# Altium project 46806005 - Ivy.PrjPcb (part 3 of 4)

## Sheet 620_Ethernet2.SchDoc: Ivy - Verdin Industrial Board Rev 1.1
size Letter; Organization: Toradex Solutions Inc.; Address1: 6415 Northwest Drive; Address2: Mississauga, ON, L4V 1X1; Address3: Canada
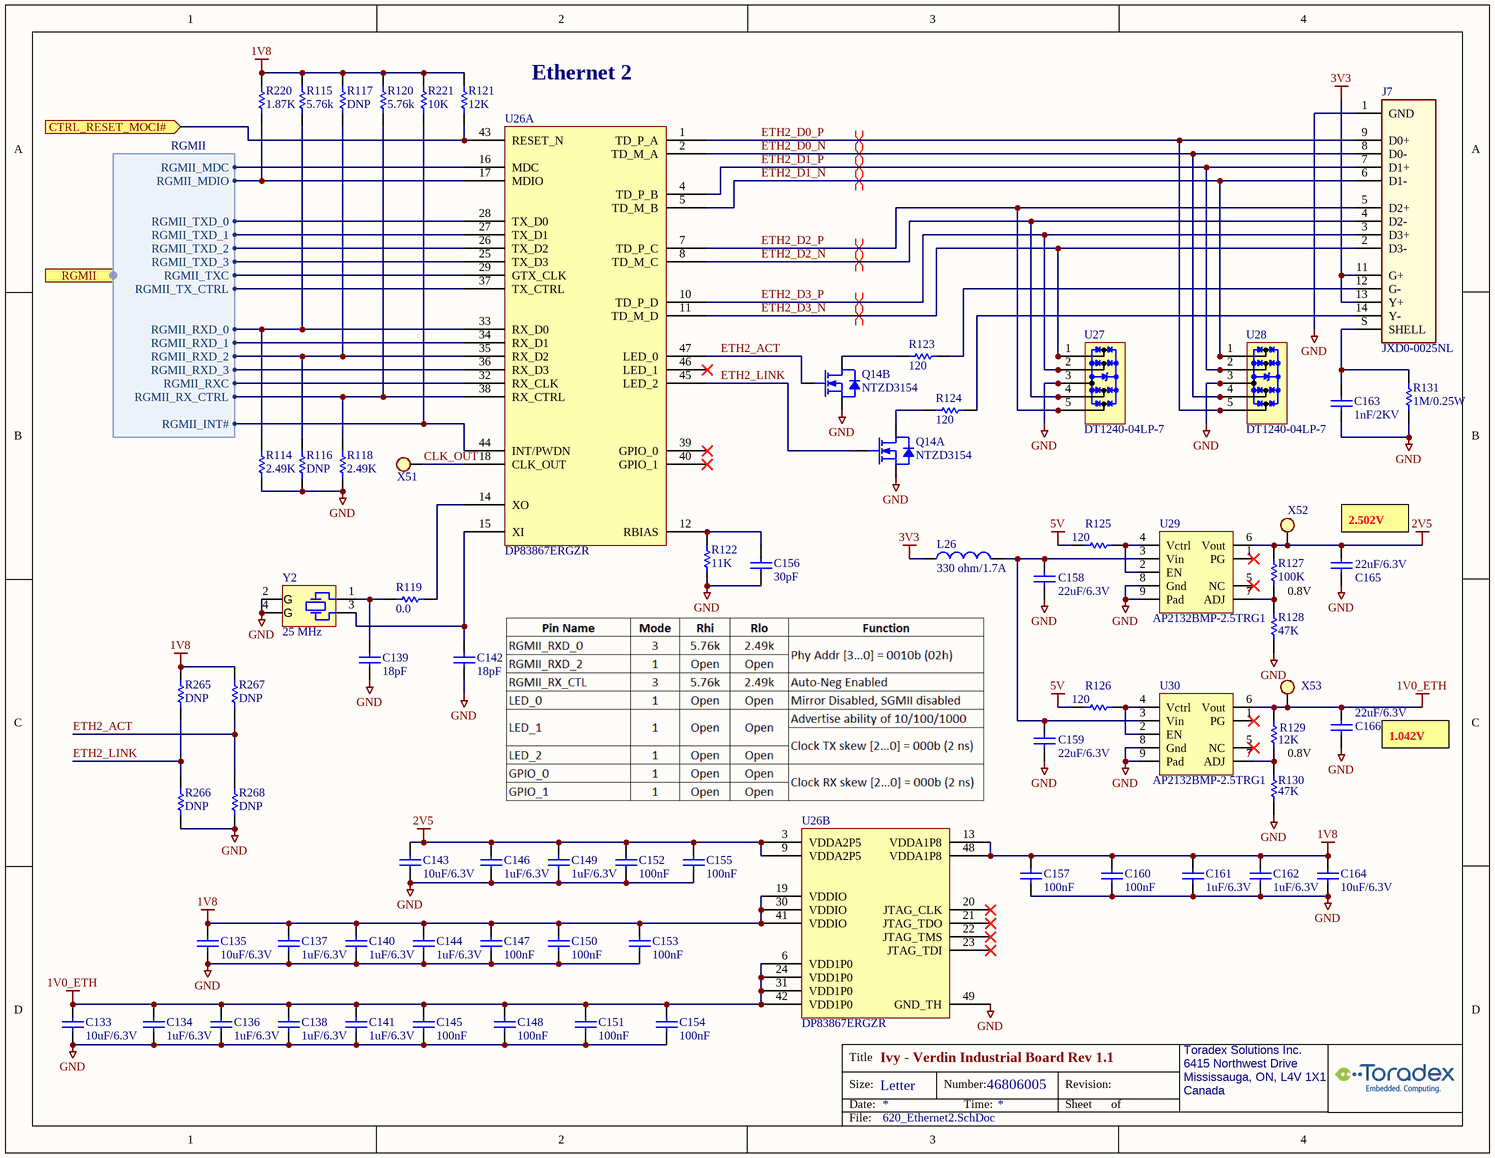
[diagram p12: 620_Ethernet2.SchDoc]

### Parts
C133  value 10uF/6.3V  [C0402_CAPC1005L]  (hidden comment: 1646-Cap-0402-10uF/6.3V)
C134  value 1uF/6.3V  [C0402_CAPC1005L]  (hidden comment: 1006-Cap-0402-1uF/6V3)
C135  value 10uF/6.3V  [C0402_CAPC1005L]  (hidden comment: 1646-Cap-0402-10uF/6.3V)
C136  value 1uF/6.3V  [C0402_CAPC1005L]  (hidden comment: 1006-Cap-0402-1uF/6V3)
C137  value 1uF/6.3V  [C0402_CAPC1005L]  (hidden comment: 1006-Cap-0402-1uF/6V3)
C138  value 1uF/6.3V  [C0402_CAPC1005L]  (hidden comment: 1006-Cap-0402-1uF/6V3)
C139  value 18pF  [C0402_CAPC1005L]  (hidden comment: 0321-Cap-0402-18pF/50V)
C140  value 1uF/6.3V  [C0402_CAPC1005L]  (hidden comment: 1006-Cap-0402-1uF/6V3)
C141  value 1uF/6.3V  [C0402_CAPC1005L]  (hidden comment: 1006-Cap-0402-1uF/6V3)
C142  value 18pF  [C0402_CAPC1005L]  (hidden comment: 0321-Cap-0402-18pF/50V)
C143  value 10uF/6.3V  [C0402_CAPC1005L]  (hidden comment: 1646-Cap-0402-10uF/6.3V)
C144  value 1uF/6.3V  [C0402_CAPC1005L]  (hidden comment: 1006-Cap-0402-1uF/6V3)
C145  100nF  [C0402_CAPC1005L]
C146  value 1uF/6.3V  [C0402_CAPC1005L]  (hidden comment: 1006-Cap-0402-1uF/6V3)
C147  100nF  [C0402_CAPC1005L]
C148  100nF  [C0402_CAPC1005L]
C149  value 1uF/6.3V  [C0402_CAPC1005L]  (hidden comment: 1006-Cap-0402-1uF/6V3)
C150  100nF  [C0402_CAPC1005L]
C151  100nF  [C0402_CAPC1005L]
C152  100nF  [C0402_CAPC1005L]
C153  100nF  [C0402_CAPC1005L]
C154  100nF  [C0402_CAPC1005L]
C155  100nF  [C0402_CAPC1005L]
C156  value 30pF  [C/0603]  (hidden comment: 0958-Cap-0603-30pF/50V)
C157  100nF  [C0402_CAPC1005L]
C158  22uF/6.3V  [C0402_CAPC1005L]
C159  22uF/6.3V  [C0402_CAPC1005L]
C160  100nF  [C0402_CAPC1005L]
C161  value 1uF/6.3V  [C0402_CAPC1005L]  (hidden comment: 1006-Cap-0402-1uF/6V3)
C162  value 1uF/6.3V  [C0402_CAPC1005L]  (hidden comment: 1006-Cap-0402-1uF/6V3)
C163  value 1nF/2KV  [C/1206]  (hidden comment: 0567-Cap-1206-1nF/2KV)
C164  value 10uF/6.3V  [C0402_CAPC1005L]  (hidden comment: 1646-Cap-0402-10uF/6.3V)
C165  22uF/6.3V  [C0402_CAPC1005L]
C166  22uF/6.3V  [C0402_CAPC1005L]
J7  JXD0-0025NL  [PULSE_JXD0-0025NL]
L26  value 330 ohm/1.7A  [INDC1608x095]  (hidden comment: 0405-Fer-0603-330ohm/1.7A)
Q14  NTZD3154  [SOT563]  (parts A,B of 2)
R114  value 2.49K  [R0402_RESC1005L]  (hidden comment: 2313-Res-0402-2.49K)
R115  value 5.76k  [R0402_RESC1005L]  (hidden comment: 2077-Res-0402-5.76K)
R116  value DNP  [R0402_RESC1005L]  (hidden comment: 0000-Res-0402-DNP)
R117  value DNP  [R0402_RESC1005L]  (hidden comment: 0000-Res-0402-DNP)
R118  value 2.49K  [R0402_RESC1005L]  (hidden comment: 2313-Res-0402-2.49K)
R119  value 0.0  [R/0603]  (hidden comment: 0195-Res-0603-0.0ohm)
R120  value 5.76k  [R0402_RESC1005L]  (hidden comment: 2077-Res-0402-5.76K)
R121  value 12K  [R0402_RESC1005L]  (hidden comment: 1537-Res-0402-12K)
R122  value 11K  [R0402_RESC1005L]  (hidden comment: 2527-Res-0402-11K)
R123  value 120  [R0402_RESC1005L]  (hidden comment: 1552-Res-0402-120)
R124  value 120  [R0402_RESC1005L]  (hidden comment: 1552-Res-0402-120)
R125  value 120  [R0402_RESC1005L]  (hidden comment: 1552-Res-0402-120)
R126  value 120  [R0402_RESC1005L]  (hidden comment: 1552-Res-0402-120)
R127  value 100K  [R0402_RESC1005L]  (hidden comment: 1977-Res-0402-100K)
R128  value 47K  [R/0603]  (hidden comment: 0042-Res-0603-47K)
R129  value 12K  [R0402_RESC1005L]  (hidden comment: 1537-Res-0402-12K)
R130  value 47K  [R/0603]  (hidden comment: 0042-Res-0603-47K)
R131  value 1M/0.25W  [R/1206]  (hidden comment: 1860-Res-1206-1M-5%-0.25W)
R220  value 1.87K  [R0402_RESC1005L]  (hidden comment: 1536-Res-0402-1.87K)
R221  value 10K  [R0402_RESC1005L]  (hidden comment: 1572-Res-0402-10K)
R265  value DNP  [R0402_RESC1005L]  (hidden comment: 0000-Res-0402-DNP)
R266  value DNP  [R0402_RESC1005L]  (hidden comment: 0000-Res-0402-DNP)
R267  value DNP  [R0402_RESC1005L]  (hidden comment: 0000-Res-0402-DNP)
R268  value DNP  [R0402_RESC1005L]  (hidden comment: 0000-Res-0402-DNP)
U26  DP83867ERGZR  [RGZ0048B]  (parts A,B of 2)
U27  DT1240-04LP-7  [10-UFDFN]
U28  DT1240-04LP-7  [10-UFDFN]
U29  AP2132BMP-2.5TRG1  [SOP-9 TP_ALT]
U30  AP2132BMP-2.5TRG1  [SOP-9 TP_ALT]
X51  000-TestPoint2  [TestPoint_3]  (value not drawn)
X52  000-TestPoint2  [TestPoint_3]  (value not drawn)
X53  000-TestPoint2  [TestPoint_3]  (value not drawn)
Y2  value 25 MHz  [XTAL_CX3225]  (hidden comment: 0987-Xtal 25MHz 3.2x2.5mm)

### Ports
CTRL_RESET_MOCI# (in), RGMII (harness RGMII)

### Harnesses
RGMII: RGMII_TXD_0, RGMII_TXD_1, RGMII_TXD_2, RGMII_TXD_3, RGMII_TXC, RGMII_TX_CTRL, RGMII_RXD_0, RGMII_RXD_1, RGMII_RXD_2, RGMII_RXD_3, RGMII_RXC, RGMII_RX_CTRL, RGMII_MDIO, RGMII_MDC, RGMII_INT#

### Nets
1V0_ETH: C133.2 C134.2 C136.2 C138.2 C141.2 C145.2 C148.2 C151.2 C154.2 C166.2 R129.2 U26.6(VDD1P0) U26.24(VDD1P0) U26.31(VDD1P0) U26.42(VDD1P0) U30.6(Vout) X53.1
1V8: C135.2 C137.2 C140.2 C144.2 C147.2 C150.2 C153.2 C157.2 C160.2 C161.2 C162.2 C164.2 R115.2 R117.1 R120.2 R121.2 R220.2 R221.2 R265.1 R267.1 U26.13(VDDA1P8) U26.19(VDDIO) U26.30(VDDIO) U26.41(VDDIO) U26.48(VDDA1P8)
2V5: C143.2 C146.2 C149.2 C152.2 C155.2 C165.2 R127.2 U26.3(VDDA2P5) U26.9(VDDA2P5) U29.6(Vout) X52.1
3V3: J7.11(G+) J7.13(Y+) L26.1
5V: R125.2 R126.2
GND: C133.1 C134.1 C135.1 C136.1 C137.1 C138.1 C139.1 C140.1 C141.1 C142.1 C143.1 C144.1 C145.1 C146.1 C147.1 C148.1 C149.1 C150.1 C151.1 C152.1 C153.1 C154.1 C155.1 C156.1 C157.1 C158.1 C159.1 C160.1 C161.1 C162.1 C163.1 C164.1 C165.1 C166.1 J7.1(GND) Q14.1(S) Q14.4(S) R114.1 R116.1 R118.1 R122.2 R128.2 R130.2 R131.2 R266.2 R268.2 U26.49(GND_TH) U27.3(GND) U27.8(GND) U28.3(GND) U28.8(GND) U29.8(Gnd) U29.9(Pad) U30.8(Gnd) U30.9(Pad) Y2.2(GND) Y2.4(GND)
CLK_OUT: U26.18(CLK_OUT) X51.1
CTRL_RESET_MOCI#: R121.1 U26.43(RESET_N) ; port CTRL_RESET_MOCI#
ETH2_ACT: Q14.5(G) R267.2 R268.1 U26.47(LED_0)
ETH2_D0_N: J7.8(D0-) U26.2(TD_M_A) U28.4(IO3) U28.7(NC)
ETH2_D0_P: J7.9(D0+) U26.1(TD_P_A) U28.5(IO4) U28.6(NC)
ETH2_D1_N: J7.6(D1-) U26.5(TD_M_B) U28.1(IO1) U28.10(NC)
ETH2_D1_P: J7.7(D1+) U26.4(TD_P_B) U28.2(IO2) U28.9(NC)
ETH2_D2_N: J7.4(D2-) U26.8(TD_M_C) U27.4(IO3) U27.7(NC)
ETH2_D2_P: J7.5(D2+) U26.7(TD_P_C) U27.5(IO4) U27.6(NC)
ETH2_D3_N: J7.2(D3-) U26.11(TD_M_D) U27.1(IO1) U27.10(NC)
ETH2_D3_P: J7.3(D3+) U26.10(TD_P_D) U27.2(IO2) U27.9(NC)
ETH2_LINK: Q14.2(G) R265.2 R266.1 U26.45(LED_2)
NetC139_2: C139.2 R119.2 Y2.1
NetC142_2: C142.2 U26.15(XI) Y2.3
NetC156_2: C156.2 R122.1 U26.12(RBIAS)
NetC158_2: C158.2 C159.2 L26.2 U29.3(Vin) U30.3(Vin)
NetC163_2: C163.2 J7.S(SHELL) R131.1
NetJ7_12: J7.12(G-) R123.2
NetJ7_14: J7.14(Y-) R124.2
NetM1_189: R221.1 U26.44(INT/PWDN) ; port RGMII.RGMII_INT#
NetM1_191: R220.1 U26.17(MDIO) ; port RGMII.RGMII_MDIO
NetM1_193: U26.16(MDC) ; port RGMII.RGMII_MDC
NetM1_197: U26.32(RX_CLK) ; port RGMII.RGMII_RXC
NetM1_199: R118.2 R120.1 U26.38(RX_CTRL) ; port RGMII.RGMII_RX_CTRL
NetM1_201: R114.2 R115.1 U26.33(RX_D0) ; port RGMII.RGMII_RXD_0
NetM1_203: U26.34(RX_D1) ; port RGMII.RGMII_RXD_1
NetM1_205: R116.2 R117.2 U26.35(RX_D2) ; port RGMII.RGMII_RXD_2
NetM1_207: U26.36(RX_D3) ; port RGMII.RGMII_RXD_3
NetM1_211: U26.37(TX_CTRL) ; port RGMII.RGMII_TX_CTRL
NetM1_213: U26.29(GTX_CLK) ; port RGMII.RGMII_TXC
NetM1_215: U26.25(TX_D3) ; port RGMII.RGMII_TXD_3
NetM1_217: U26.26(TX_D2) ; port RGMII.RGMII_TXD_2
NetM1_219: U26.27(TX_D1) ; port RGMII.RGMII_TXD_1
NetM1_221: U26.28(TX_D0) ; port RGMII.RGMII_TXD_0
NetQ14_3: Q14.3(D) R123.1
NetQ14_6: Q14.6(D) R124.1
NetR119_1: R119.1 U26.14(XO)
NetR125_1: R125.1 U29.2(EN) U29.4(Vctrl)
NetR126_1: R126.1 U30.2(EN) U30.4(Vctrl)
NetR127_1: R127.1 R128.1 U29.7(ADJ)
NetR129_1: R129.1 R130.1 U30.7(ADJ)

Not connected (* = marked no-connect by the designer): U26 20(JTAG_CLK)* 21(JTAG_TDO)* 22(JTAG_TMS)* 23(JTAG_TDI)* 39(GPIO_0)* 40(GPIO_1)* 46(LED_1)*; U29 1(PG)* 5(NC)*; U30 1(PG)* 5(NC)*

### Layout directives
differential pair; differential pair class ETH2: ETH2_D0_N, ETH2_D0_P, ETH2_D1_N, ETH2_D1_P, ETH2_D2_N, ETH2_D2_P, ETH2_D3_N, ETH2_D3_P

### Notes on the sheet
- Ethernet 2
- (near C165) 2.502V
- 0.8V
- (near C166) 1.042V

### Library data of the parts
C133 C135 C143 C164 = 1646-Cap-0402-10uF/6.3V: (-55 to 85 DegC) CAP CER 10UF 6.3V 20% X5R 0402; MfrNo: GRM155R60J106ME44D; Mfr: Murata; Alt: GRM155R60J106ME47D,C0402C106M9PACTU,04026D106MAT2A; PN: 1646
C134 C136-C138 C140 C141 C144 C146 C149 C161 C162 = 1006-Cap-0402-1uF/6V3: Cap Ceramic 1uF 6.3V X5R 20% SMD 0402 85C T/R; Mfr: Samsung; MfrNo: CL05A105MQ5NNNC; Alt: CL05A105MP5NNNC,CL05A105KQ5NNNC,CL05A105KP5NNNC,CL05A105JQ5NNNC; PN: 1006; Desc: Cap Ceramic 1uF 6.3V X5R 20% SMD 0402 85C Paper T/R
C139 C142 = 0321-Cap-0402-18pF/50V: CAP CER 18PF 50V 5% NP0 0402; MfrNo: CL05C180JB5NNNC; Mfr: Samsung Electro-Mechanics America, Inc; PN: 321; Alt: 311-1415-1-ND; Alt2: 490-5858-1-ND
C145 C147 C148 C150-C155 C157 C160 = 1566-Cap-0402-100nF/50V: (-55 to 125 DegC AEC) Cap Ceramic 0.1uF 50V X7R 10% 0402; MfrNo: GRT155R71H104KE01D; Mfr: Murata; Alt: CL05B104KB54PNC,GCM155R71H104ME02D,GCM155R71H104KE02D,GCM155R71H104KE02J; PN: 1566
C156 = 0958-Cap-0603-30pF/50V: (-55 - 125 DegC) CAP CER 30PF 50V C0G/NP0 0603; Mfr: Kyocera AVX; MfrNo: 06035A300JAT2A\4K; PN: 958; Alt: CC0603GRNPO9BN300,06031A300J4T2A
C158 C159 C165 C166 = 2404-Cap-0402-22uF/6.3V: (-55 to 85 DegC) CAP CER 22UF 6.3V 20% X5R 0402; Mfr: Murata; MfrNo: GRM155R60J226ME11D; PN: 2404
C163 = 0567-Cap-1206-1nF/2KV: CAP CER 1000PF 2KV X7R 1206; Mfr: Johanson Dielectrics Inc.; MfrNo: 202R18W102KV4E; PN: 567; Alt: 478-2956-1-ND; Alt2: 399-4819-1-ND
J7 = 1380-Conn-RJ45-GBe: (-40 to 85 DegC) CONN MAGJACK 1PORT 1000 BASE-T Isolated Taps; Mfr: Pulse; PN: 1380
L26 = 0405-Fer-0603-330ohm/1.7A: (-55 to 125 DegC) FERRITE BEAD 330 OHM 0603 1.7A 80mohm, typ 48mohm; Mfr: TDK Corporation; MfrNo: MPZ1608S331ATA00; PN: 405; TR: 445-5221-2-ND; DR: 445-5221-6-ND; DR2: 810-MPZ1608S331ATA00
Q14 = 1146-NTZD3154NT1G: (-55 to 150 DegC) MOSFET 2N-CH (dual) 20V 0.54A SOT-563 1.6x1.6mm Vth:1V Ron typ:400m@4.5V, 500m@2.5V, 700m@1.8V; Mfr: ON Semiconductor; PN: 1146; Alt: NTZD3154NT5G,PMDT290UNE,115
R114 R118 = 2313-Res-0402-2.49K: (-55 to 155 DegC) RES SMD 2.49K OHM 1% 1/16W 0402 100ppm; Mfr: Yageo; MfrNo: RC0402FR-072K49L; PN: 2313
R115 R120 = 2077-Res-0402-5.76K: (-55 to 155 DegC) RES 5.76K OHM 1/16W 1% 0402 SMD; Mfr: Stackpole Electronics; MfrNo: RMCF0402FT5K76; PN: 2077
R116 R117 R265-R268 = 0000-Res-0402-DNP: RES 0402
R119 = 0195-Res-0603-0.0ohm: RES 0.0 OHM 1/10W JUMP 0603; Mfr: Samsung; MfrNo: RC1608J000CS; Alt: 311-0.0GRCT-ND; PN: 195; Alt2: A106051CT-ND; TR: 1276-3510-2-ND
R121 = 1537-Res-0402-12K: (-55 to 155 DegC AEC) RES 12K OHM 1% 1/16W 100ppm 0402; Mfr: Stackpole Electronics; MfrNo: RMCF0402FT12K0; Alt: AC0402FR-0712KL,CRGCQ0402F12K; PN: 1537
R122 = 2527-Res-0402-11K: (-55 to 155 DegC AEC) RES SMD 11K OHM 1% 1/16W 0402 100ppm 0402; Mfr: Yageo; MfrNo: AC0402FR-0711KL; PN: 2527
R123-R126 = 1552-Res-0402-120: (-55 to 155 DegC AEC) RES 120 OHM 1% 1/16W 100ppm 0402; MfrNo: RMCF0402FT120R; Mfr: Stackpole Electronics; PN: 1552; Alt: AC0402FR-07120RL,CRGCQ0402F120R
R127 = 1977-Res-0402-100K: (-55 to 155 DegC) RES 100K OHM 1/16W 1% 0402 SMD; Mfr: Yageo; MfrNo: RC0402FR-07100KL; PN: 1977
R128 = 0042-Res-0603-47K: RES 47.0K OHM 1/10W 1% 0603 SMD; Mfr: Yageo; MfrNo: RC0603FR-0747KL; Alt: RHM47.0KCFCT-ND; Alt2: RHM47.0KHCT-ND; PN: 42; TR: 311-47.0KHRTR-ND
R129 = 1537-Res-0402-12K: (-55 to 155 DegC AEC) RES 12K OHM 1% 1/16W 100ppm 0402; Mfr: Stackpole Electronics; MfrNo: RMCF0402FT12K0; PN: 1537; Alt: AC0402FR-0712KL,CRGCQ0402F12K
R130 = 0042-Res-0603-47K: (-55 to 155 DegC) RES 47.0K OHM 1/10W 1% 0603 SMD; Mfr: Yageo; MfrNo: RC0603FR-0747KL; Alt: RHM47.0KCFCT-ND; Alt2: RHM47.0KHCT-ND; PN: 42; TR: 311-47.0KHRTR-ND
R131 = 1860-Res-1206-1M-5%-0.25W: (-55 to 155 DegC) RES SMD 1M OHM 5% 0.25W 10ppm 1206; Mfr: TE Connectivity; MfrNo: CRGCQ1206J1M0; PN: 1860; Alt: RMCF1206JT1M00, RMCF1206JG1M00, CR1206-JW-105ELF
R220 = 1536-Res-0402-1.87K: (-55 to 155 DegC AEC) RES 1.87K OHM 1% 1/16W 100ppm 0402; MfrNo: RMCF0402FT1K87; Mfr: Stackpole Electronics; Alt: AC0402FR-071K87L,RK73H1ETTP1871F,ERJ-2RKF1871X; PN: 1536
R221 = 1572-Res-0402-10K: (-55 to 155 DegC AEC) RES 10K OHM 1% 1/16W 100ppm 0402; Mfr: Stackpole Electronics; MfrNo: RMCF0402FT10K0; Alt: AC0402FR-0710KL,AC0402FR-1310KL,CRGCQ0402F10K; PN: 1572
U26 = 2076-DP83867ERGZR: (-40 to 105 DegC) Eth Phy RGMII 1GBASE-T VQFN-48; Mfr: Texas Instruments; PN: 2076
U27 U28 = 1657-DT1240-04LP-7: (-55 to 85 DegC) IC TVS DIODE 4ch Vrm:5.5V Vcl:11V@5.5A 10-UFDFN 0.5mm; Mfr: Diodes; PN: 1657
U29 U30 = 1467-AP2132BMP-2.5: (-40 to 85 DegC) IC REG LDO LINEAR POS ADJ 5V 2A 8SO; Mfr: Diodes; PN: 1467; Desc: (-40 to 85 DegC) IC REG BUCK ADJ Sync 5A Vin:3.8 to 40V 100-2200kHz FSS (spread spectrum) MaxDuty:100% SO-8EP; Note: These can be also used with adjust Voltage circuit: AP2132BMP-1.2TRG1, AP2132BMP-1.5TRG1
X51-X53 = 000-TestPoint2: TestPoint SMD; Note: PCB footprint only, no parts to buy or assemble
Y2 = 0987-Xtal 25MHz 3.2x2.5mm: (-40 to 85 DegC) CRYSTAL 25.0MHZ 18PF SMD +-50ppm +-20ppm 3.2x2.5mm; MfrNo: LFXTAL055299REEL; Mfr: IQD Frequency Products; PN: 987; Note: caps: 18pF

## Sheet 820_MicroSD.SchDoc: Ivy - Verdin Industrial Board Rev 1.1
size Letter; Organization: Toradex Solutions Inc.; Address1: 6415 Northwest Drive; Address2: Mississauga, ON, L4V 1X1; Address3: Canada
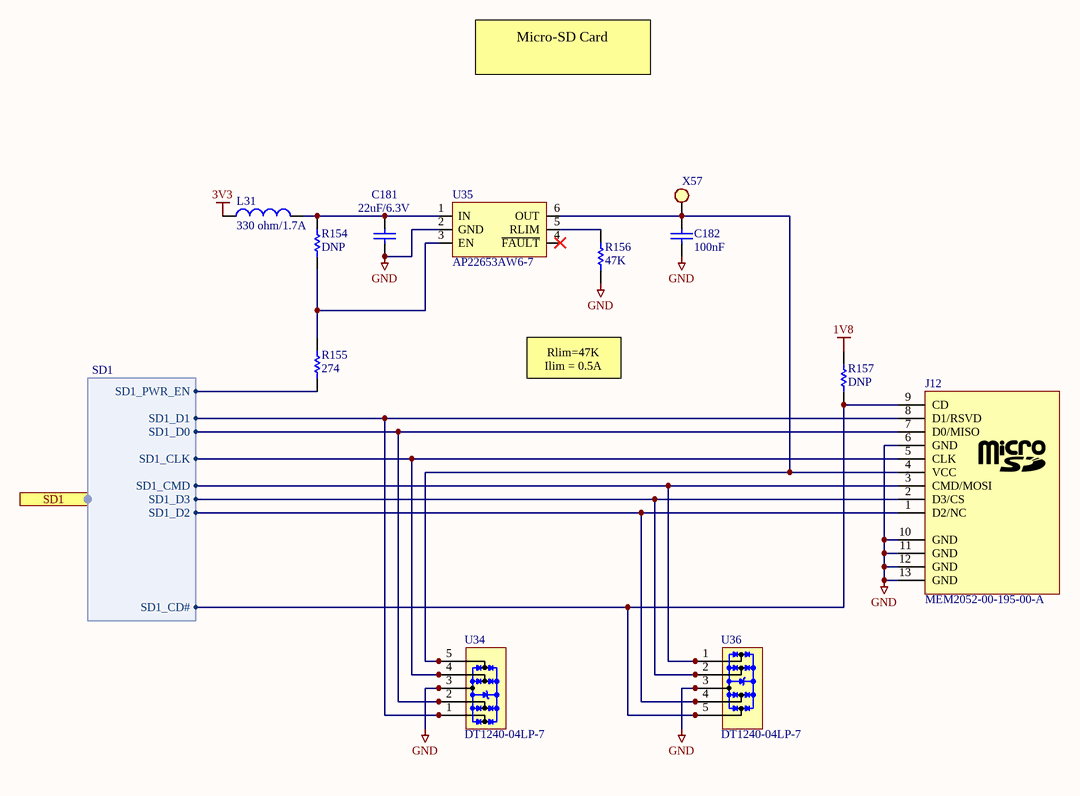
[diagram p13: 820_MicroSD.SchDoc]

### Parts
C181  22uF/6.3V  [C0402_CAPC1005L]
C182  100nF  [C0402_CAPC1005L]
J12  MEM2052-00-195-00-A  [MEM2051-00-195-00-A_revC]
L31  value 330 ohm/1.7A  [INDC1608x095]  (hidden comment: 0405-Fer-0603-330ohm/1.7A)
R154  value DNP  [R/0603]  (hidden comment: 0000-Res-0603-DNP)
R155  value 274  [R/0603]  (hidden comment: 0728-Res-0603-274ohm)
R156  value 47K  [R/0603]  (hidden comment: 0042-Res-0603-47K)
R157  value DNP  [R/0603]  (hidden comment: 0000-Res-0603-DNP)
U34  DT1240-04LP-7  [10-UFDFN]
U35  AP22653AW6-7  [sot23-6]
U36  DT1240-04LP-7  [10-UFDFN]
X57  000-TestPoint2  [TestPoint_3]  (value not drawn)

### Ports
SD1 (harness SD1)

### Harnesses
SD1: SD1_D2, SD1_D3, SD1_CMD, SD1_PWR_EN, SD1_CLK, SD1_D0, SD1_D1, SD1_CD#

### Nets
1V8: R157.2
3V3: L31.1
GND: C181.1 C182.1 J12.6(GND) J12.10(GND) J12.11(GND) J12.12(GND) J12.13(GND) R156.2 U34.3(GND) U34.8(GND) U35.2(GND) U36.3(GND) U36.8(GND)
SD1_CD#: J12.9(CD) R157.1 U36.5(IO4) U36.6(NC) ; port SD1.SD1_CD#
SD1_CLK: J12.5(CLK) U34.4(IO3) U34.7(NC) ; port SD1.SD1_CLK
SD1_CMD: J12.3(CMD/MOSI) U36.1(IO1) U36.10(NC) ; port SD1.SD1_CMD
SD1_D0: J12.7(D0/MISO) U34.2(IO2) U34.9(NC) ; port SD1.SD1_D0
SD1_D1: J12.8(D1/RSVD) U34.1(IO1) U34.10(NC) ; port SD1.SD1_D1
SD1_D2: J12.1(D2/NC) U36.4(IO3) U36.7(NC) ; port SD1.SD1_D2
SD1_D3: J12.2(D3/CS) U36.2(IO2) U36.9(NC) ; port SD1.SD1_D3
SD1_PWR_EN: R155.2 ; port SD1.SD1_PWR_EN
NetC181_2: C181.2 L31.2 R154.2 U35.1(IN)
NetC182_2: C182.2 J12.4(VCC) U34.5(IO4) U34.6(NC) U35.6(OUT) X57.1
NetR154_1: R154.1 R155.1 U35.3(EN)
NetR156_1: R156.1 U35.5(RLIM)

Not connected (* = marked no-connect by the designer): U35 4(~{FAULT})*

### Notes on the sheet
- Micro-SD Card
- Rlim=47K
  Ilim = 0.5A

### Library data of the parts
C181 = 2404-Cap-0402-22uF/6.3V: (-55 to 85 DegC) CAP CER 22UF 6.3V 20% X5R 0402; MfrNo: GRM155R60J226ME11D; Mfr: Murata; PN: 2404
C182 = 1566-Cap-0402-100nF/50V: as C145 on sheet 620_Ethernet2
J12 = 1776-Conn-MicroSD: (-40 to 85 DegC) CONN MICRO SD CARD PUSH-PUSH R/A, OPEN; Mfr: Global Connector Technology; PN: 1776; Alt: PN 1404
L31 = 0405-Fer-0603-330ohm/1.7A: as L26 on sheet 620_Ethernet2
R154 R157 = 0000-Res-0603-DNP: RES 0603
R155 = 0728-Res-0603-274ohm: RES SMD 274 OHM 1% 1/10W 0603; MfrNo: RC0603FR-07274RL; Mfr: Yageo; PN: 728; TR: 311-274HRTR-ND
R156 = 0042-Res-0603-47K: as R128 on sheet 620_Ethernet2
U34 U36 = 1657-DT1240-04LP-7: as U27 on sheet 620_Ethernet2
U35 = 1475-AP22653: (-40 to 85 DegC) IC PWR SWITCH 3-5.5V EN-Active-High ENth:1.5V With-Discharge 65mohm typ ADJ 0.1-2.1A 6SSOP; Mfr: Diodes; PN: 1475; Note: Similar: BD2222G, BD2242G, TPS25221, TPS2553, RT9728A, RT9728B, RT9728C, AP2553, MIC2009YM6, MIC2019YM6, MIC2009A-1YM6,MIC2019A-1YM6
X57 = 000-TestPoint2: as X51-X53 on sheet 620_Ethernet2

## Sheet 840_ADC.SchDoc: Ivy - Verdin Industrial Board Rev 1.1
size 566 x 398 mm; Organization: Toradex Solutions Inc.; Address1: 6415 Northwest Drive; Address2: Mississauga, ON, L4V 1X1; Address3: Canada
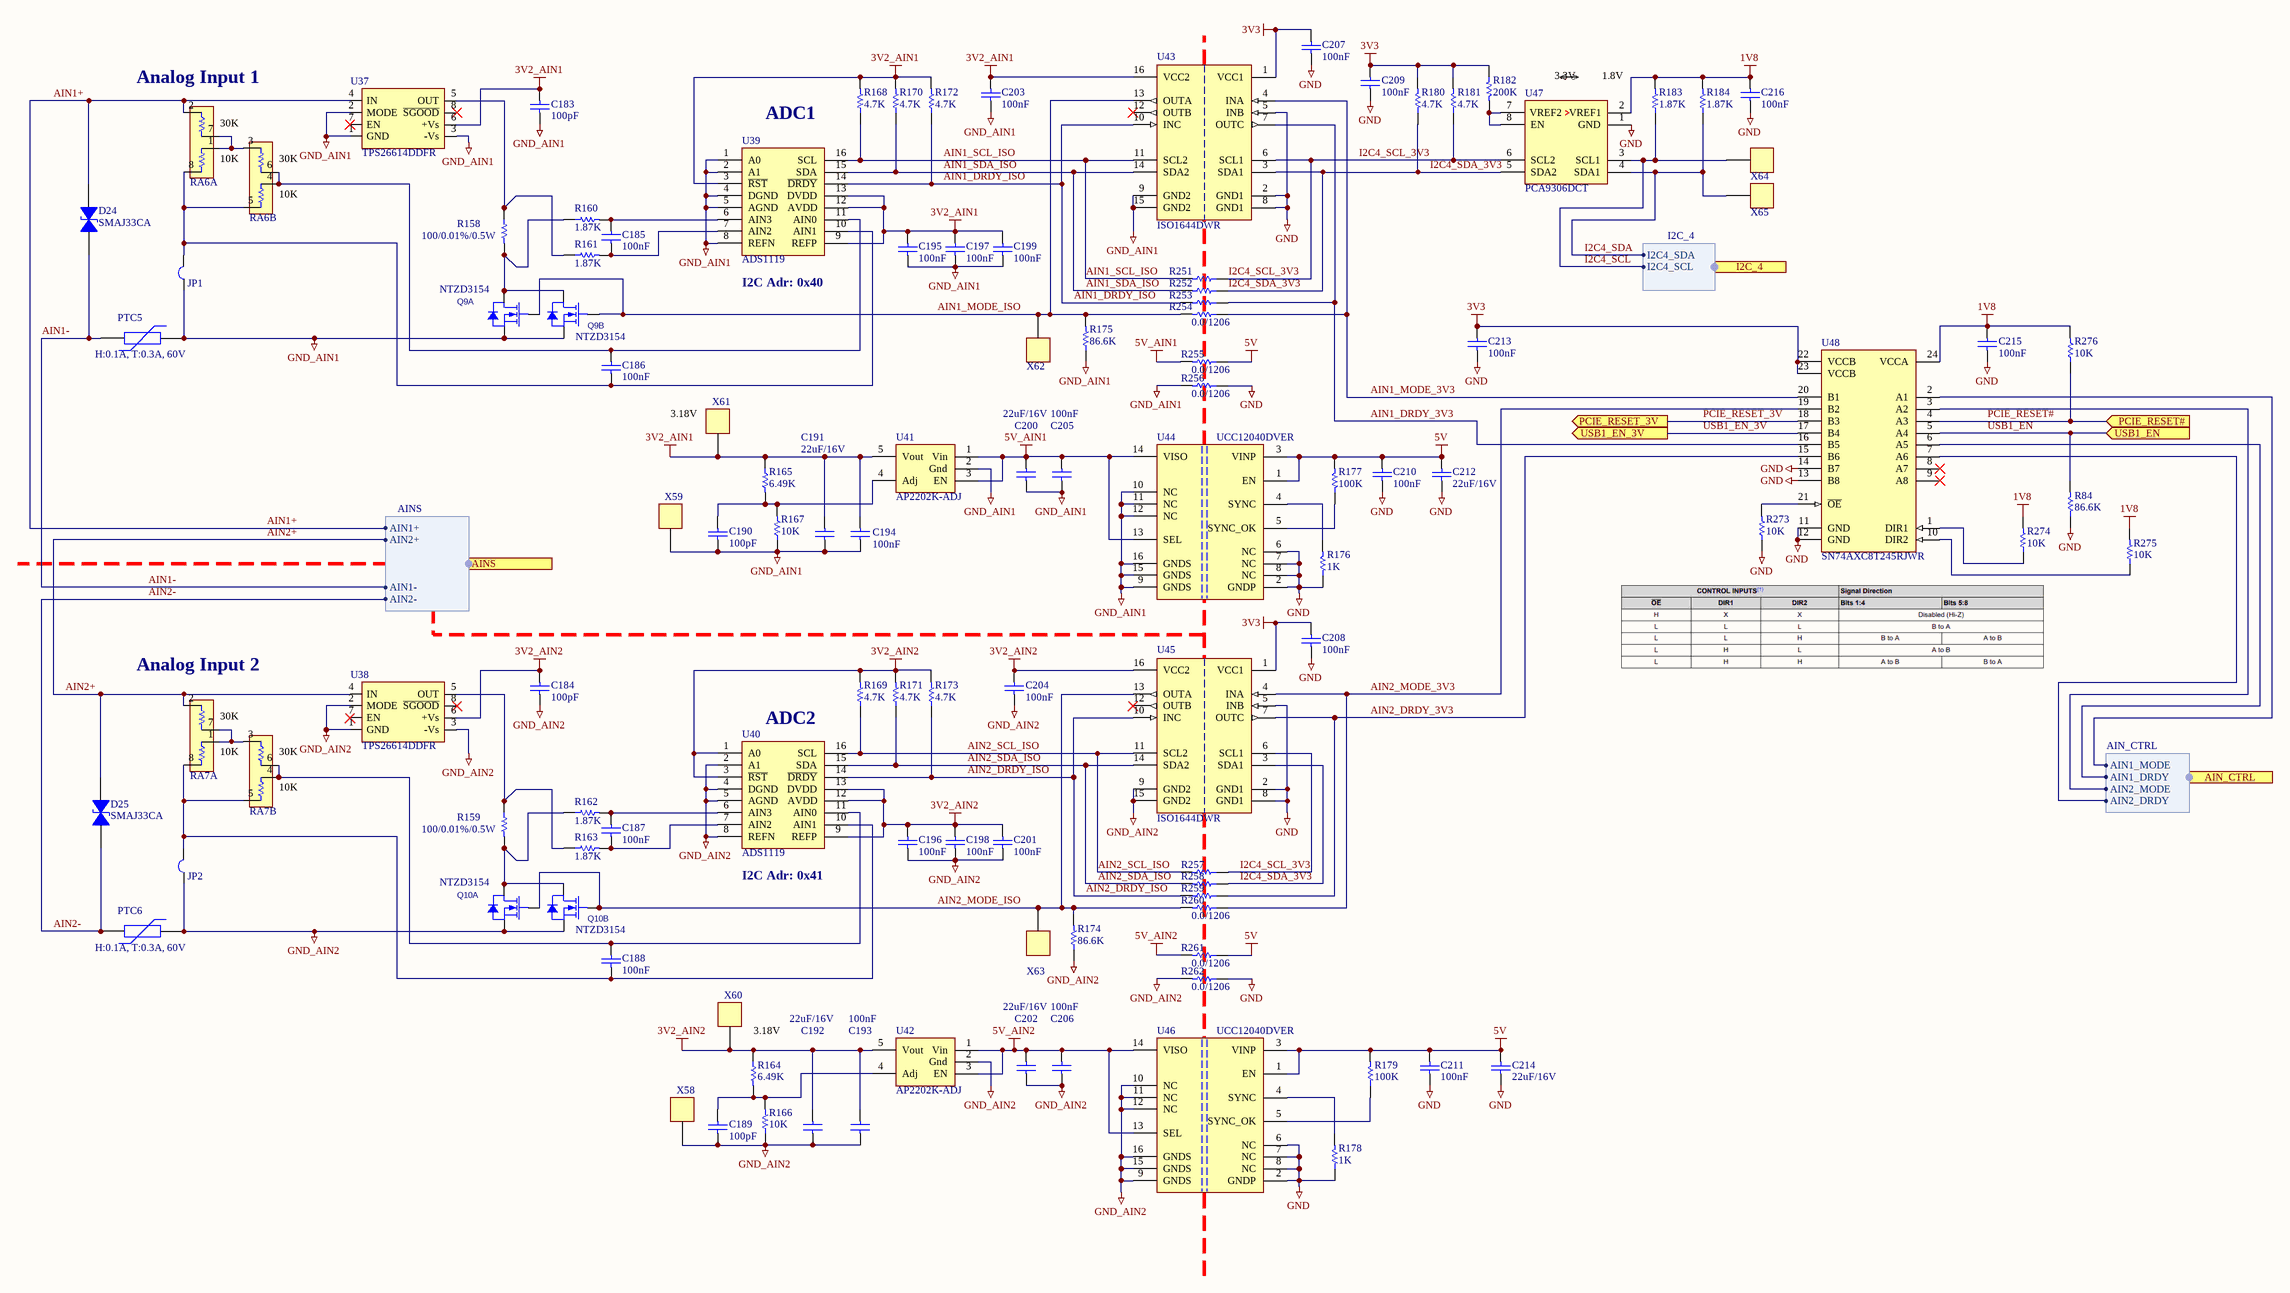
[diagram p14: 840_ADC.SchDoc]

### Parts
C183  value 100pF  [C0402_CAPC1005L]  (hidden comment: 1602-Cap-0402-100pF)
C184  value 100pF  [C0402_CAPC1005L]  (hidden comment: 1602-Cap-0402-100pF)
C185  100nF  [C0402_CAPC1005L]
C186  100nF  [C0402_CAPC1005L]
C187  100nF  [C0402_CAPC1005L]
C188  100nF  [C0402_CAPC1005L]
C189  value 100pF  [C0402_CAPC1005L]  (hidden comment: 1602-Cap-0402-100pF)
C190  value 100pF  [C0402_CAPC1005L]  (hidden comment: 1602-Cap-0402-100pF)
C191  value 22uF/16V  [C/0805]  (hidden comment: 1314-Cap-0805-22uF/16V)
C192  value 22uF/16V  [C/0805]  (hidden comment: 1314-Cap-0805-22uF/16V)
C193  100nF  [C0402_CAPC1005L]
C194  100nF  [C0402_CAPC1005L]
C195  100nF  [C0402_CAPC1005L]
C196  100nF  [C0402_CAPC1005L]
C197  100nF  [C0402_CAPC1005L]
C198  100nF  [C0402_CAPC1005L]
C199  100nF  [C0402_CAPC1005L]
C200  value 22uF/16V  [C/0805]  (hidden comment: 1314-Cap-0805-22uF/16V)
C201  100nF  [C0402_CAPC1005L]
C202  value 22uF/16V  [C/0805]  (hidden comment: 1314-Cap-0805-22uF/16V)
C203  100nF  [C0402_CAPC1005L]
C204  100nF  [C0402_CAPC1005L]
C205  100nF  [C0402_CAPC1005L]
C206  100nF  [C0402_CAPC1005L]
C207  100nF  [C0402_CAPC1005L]
C208  100nF  [C0402_CAPC1005L]
C209  100nF  [C0402_CAPC1005L]
C210  100nF  [C0402_CAPC1005L]
C211  100nF  [C0402_CAPC1005L]
C212  value 22uF/16V  [C/0805]  (hidden comment: 1314-Cap-0805-22uF/16V)
C213  100nF  [C0402_CAPC1005L]
C214  value 22uF/16V  [C/0805]  (hidden comment: 1314-Cap-0805-22uF/16V)
C215  100nF  [C0402_CAPC1005L]
C216  100nF  [C0402_CAPC1005L]
D24  SMAJ33CA  [SMAJ_TRANSIL]
D25  SMAJ33CA  [SMAJ_TRANSIL]
JP1  Short  [Short_040]  (value not drawn)
JP2  Short  [Short_040]  (value not drawn)
PTC5  H:0.1A, T:0.3A, 60V  [PTC_1812]
PTC6  H:0.1A, T:0.3A, 60V  [PTC_1812]
Q9  NTZD3154  [SOT563]  (parts A,B of 2)
Q10  NTZD3154  [SOT563]  (parts A,B of 2)
R84  value 86.6K  [R0402_RESC1005L]  (hidden comment: 1539-Res-0402-86.6k)
R158  value 100/0.01%/0.5W  [R/1206]  (hidden comment: 1192-Res-1206-100ohm-0.01%-0.5W)
R159  value 100/0.01%/0.5W  [R/1206]  (hidden comment: 1192-Res-1206-100ohm-0.01%-0.5W)
R160  value 1.87K  [R0402_RESC1005L]  (hidden comment: 1536-Res-0402-1.87K)
R161  value 1.87K  [R0402_RESC1005L]  (hidden comment: 1536-Res-0402-1.87K)
R162  value 1.87K  [R0402_RESC1005L]  (hidden comment: 1536-Res-0402-1.87K)
R163  value 1.87K  [R0402_RESC1005L]  (hidden comment: 1536-Res-0402-1.87K)
R164  value 6.49K  [R0402_RESC1005L]  (hidden comment: 1018-Res-0402-6.49K)
R165  value 6.49K  [R0402_RESC1005L]  (hidden comment: 1018-Res-0402-6.49K)
R166  value 10K  [R0402_RESC1005L]  (hidden comment: 1572-Res-0402-10K)
R167  value 10K  [R0402_RESC1005L]  (hidden comment: 1572-Res-0402-10K)
R168  value 4.7K  [R0402_RESC1005L]  (hidden comment: 2233-Res-0402-4.7K)
R169  value 4.7K  [R0402_RESC1005L]  (hidden comment: 2233-Res-0402-4.7K)
R170  value 4.7K  [R0402_RESC1005L]  (hidden comment: 2233-Res-0402-4.7K)
R171  value 4.7K  [R0402_RESC1005L]  (hidden comment: 2233-Res-0402-4.7K)
R172  value 4.7K  [R0402_RESC1005L]  (hidden comment: 2233-Res-0402-4.7K)
R173  value 4.7K  [R0402_RESC1005L]  (hidden comment: 2233-Res-0402-4.7K)
R174  value 86.6K  [R0402_RESC1005L]  (hidden comment: 1539-Res-0402-86.6k)
R175  value 86.6K  [R0402_RESC1005L]  (hidden comment: 1539-Res-0402-86.6k)
R176  value 1K  [R0402_RESC1005L]  (hidden comment: 1650-Res-0402-1K)
R177  value 100K  [R0402_RESC1005L]  (hidden comment: 1977-Res-0402-100K)
R178  value 1K  [R0402_RESC1005L]  (hidden comment: 1650-Res-0402-1K)
R179  value 100K  [R0402_RESC1005L]  (hidden comment: 1977-Res-0402-100K)
R180  value 4.7K  [R0402_RESC1005L]  (hidden comment: 2233-Res-0402-4.7K)
R181  value 4.7K  [R0402_RESC1005L]  (hidden comment: 2233-Res-0402-4.7K)
R182  value 200K  [R/0603]  (hidden comment: 1367-Res-0603-200K)
R183  value 1.87K  [R0402_RESC1005L]  (hidden comment: 1536-Res-0402-1.87K)
R184  value 1.87K  [R0402_RESC1005L]  (hidden comment: 1536-Res-0402-1.87K)
R251  0038-Res-1206-0.0ohm  [R/1206]  (value not drawn)
R252  0038-Res-1206-0.0ohm  [R/1206]  (value not drawn)
R253  0038-Res-1206-0.0ohm  [R/1206]  (value not drawn)
R254  value 0.0/1206  [R/1206]  (hidden comment: 0038-Res-1206-0.0ohm)
R255  value 0.0/1206  [R/1206]  (hidden comment: 0038-Res-1206-0.0ohm)
R256  value 0.0/1206  [R/1206]  (hidden comment: 0038-Res-1206-0.0ohm)
R257  0038-Res-1206-0.0ohm  [R/1206]  (value not drawn)
R258  0038-Res-1206-0.0ohm  [R/1206]  (value not drawn)
R259  0038-Res-1206-0.0ohm  [R/1206]  (value not drawn)
R260  value 0.0/1206  [R/1206]  (hidden comment: 0038-Res-1206-0.0ohm)
R261  value 0.0/1206  [R/1206]  (hidden comment: 0038-Res-1206-0.0ohm)
R262  value 0.0/1206  [R/1206]  (hidden comment: 0038-Res-1206-0.0ohm)
R273  value 10K  [R0402_RESC1005L]  (hidden comment: 1572-Res-0402-10K)
R274  value 10K  [R0402_RESC1005L]  (hidden comment: 1572-Res-0402-10K)
R275  value 10K  [R0402_RESC1005L]  (hidden comment: 1572-Res-0402-10K)
R276  value 10K  [R0402_RESC1005L]  (hidden comment: 1572-Res-0402-10K)
RA6  2066A-ResArr-1206-10kohm-30kohm  [RESNET-1206-4]  (value not drawn)  (parts A,B of 2)
RA7  2066A-ResArr-1206-10kohm-30kohm  [RESNET-1206-4]  (value not drawn)  (parts A,B of 2)
U37  TPS26614DDFR  [TSOT-23-8_TEX]
U38  TPS26614DDFR  [TSOT-23-8_TEX]
U39  ADS1119  [TSSOP16]
U40  ADS1119  [TSSOP16]
U41  AP2202K-ADJ  [SOT23-5]
U42  AP2202K-ADJ  [SOT23-5]
U43  ISO1644DWR  [SOIC-16]
U44  UCC12040DVER  [SOIC-16]
U45  ISO1644DWR  [SOIC-16]
U46  UCC12040DVER  [SOIC-16]
U47  PCA9306DCT  [TSSO3x5-G8/X.35]
U48  SN74AXC8T245RJWR  [UQFN-24]
X58  000-TestPoint  [TestPoint_1]  (value not drawn)
X59  000-TestPoint  [TestPoint_1]  (value not drawn)
X60  000-TestPoint  [TestPoint_1]  (value not drawn)
X61  000-TestPoint  [TestPoint_1]  (value not drawn)
X62  000-TestPoint  [TestPoint_1]  (value not drawn)
X63  000-TestPoint  [TestPoint_1]  (value not drawn)
X64  000-TestPoint  [TestPoint_1]  (value not drawn)
X65  000-TestPoint  [TestPoint_1]  (value not drawn)

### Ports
AIN_CTRL (harness AIN_CTRL), AINS (harness AINS), I2C_4 (harness I2C_4), PCIE_RESET# (in), PCIE_RESET_3V (out), USB1_EN (in), USB1_EN_3V (out)

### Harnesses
I2C_4: I2C4_SDA, I2C4_SCL
AIN_CTRL: AIN1_MODE, AIN2_MODE, AIN1_DRDY, AIN2_DRDY
AINS: AIN1+, AIN1-, AIN2+, AIN2-

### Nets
1V8: C215.2 C216.2 R183.2 R184.2 R274.2 R275.2 R276.2 U47.2(VREF1) U48.24(VCCA)
3V2_AIN1: C183.1 C191.2 C194.1 C195.2 C197.2 C199.2 C203.2 R165.1 R168.2 R170.2 R172.2 U37.6(+Vs) U39.3(~{RST}) U39.9(REFP) U39.12(AVDD) U39.13(DVDD) U41.5(Vout) U43.16(VCC2) X61.1
3V2_AIN2: C184.1 C192.2 C193.1 C196.2 C198.2 C201.2 C204.2 R164.1 R169.2 R171.2 R173.2 U38.6(+Vs) U40.1(A0) U40.3(~{RST}) U40.9(REFP) U40.12(AVDD) U40.13(DVDD) U42.5(Vout) U45.16(VCC2) X60.1
3V3: C207.2 C208.2 C209.2 C213.2 R180.2 R181.2 R182.1 U43.1(VCC1) U45.1(VCC1) U48.22(VCCB) U48.23(VCCB)
5V: C210.1 C211.1 C212.2 C214.2 R177.2 R179.2 R255.1 R261.1 U44.1(EN) U44.3(VINP) U46.1(EN) U46.3(VINP)
5V_AIN1: C200.2 C205.1 R255.2 U41.1(Vin) U41.3(EN) U44.13(SEL) U44.14(VISO)
5V_AIN2: C202.2 C206.1 R261.2 U42.1(Vin) U42.3(EN) U46.13(SEL) U46.14(VISO)
GND: C207.1 C208.1 C209.1 C210.2 C211.2 C212.1 C213.1 C214.1 C215.1 C216.1 R84.1 R176.1 R178.1 R256.1 R262.1 R273.1 U43.2(GND1) U43.5(INB) U43.8(GND1) U44.2(GNDP) U44.6(NC) U44.7(NC) U44.8(NC) U45.2(GND1) U45.5(INB) U45.8(GND1) U46.2(GNDP) U46.6(NC) U46.7(NC) U46.8(NC) U47.1(GND) U48.11(GND) U48.12(GND) U48.13(B8) U48.14(B7)
GND_AIN1: C183.2 C190.1 C191.1 C194.2 C195.1 C197.1 C199.1 C200.1 C203.1 C205.2 JP1.1(C1) PTC5.2 Q9.1(S) Q9.4(S) R167.1 R175.1 R256.2 U37.1(GND) U37.2(MODE) U37.3(-Vs) U39.1(A0) U39.2(A1) U39.4(DGND) U39.5(AGND) U39.8(REFN) U41.2(Gnd) U43.9(GND2) U43.15(GND2) U44.9(GNDS) U44.10(NC) U44.11(NC) U44.12(NC) U44.15(GNDS) U44.16(GNDS) X59.1
GND_AIN2: C184.2 C189.1 C192.1 C193.2 C196.1 C198.1 C201.1 C202.1 C204.1 C206.2 JP2.1(C1) PTC6.2 Q10.1(S) Q10.4(S) R166.1 R174.1 R262.2 U38.1(GND) U38.2(MODE) U38.3(-Vs) U40.2(A1) U40.4(DGND) U40.5(AGND) U40.8(REFN) U42.2(Gnd) U45.9(GND2) U45.15(GND2) U46.9(GNDS) U46.10(NC) U46.11(NC) U46.12(NC) U46.15(GNDS) U46.16(GNDS) X58.1
AIN1+: D24.1 RA6.2 U37.4(IN) ; port AINS.AIN1+
AIN1-: D24.2 PTC5.1 ; port AINS.AIN1-
AIN1_DRDY_3V3: R253.1 U43.7(OUTC) U48.16(B5)
AIN1_DRDY_ISO: R172.1 R253.2 U39.14(~{DRDY}) U43.10(INC)
AIN1_MODE_3V3: R254.1 U43.4(INA) U48.20(B1)
AIN1_MODE_ISO: Q9.2(G) Q9.5(G) R175.2 R254.2 U43.13(OUTA) X62.1
AIN1_SCL_ISO: R168.1 R251.2 U39.16(SCL) U43.11(SCL2)
AIN1_SDA_ISO: R170.1 R252.2 U39.15(SDA) U43.14(SDA2)
AIN2+: D25.1 RA7.2 U38.4(IN) ; port AINS.AIN2+
AIN2-: D25.2 PTC6.1 ; port AINS.AIN2-
AIN2_DRDY_3V3: R259.1 U45.7(OUTC) U48.15(B6)
AIN2_DRDY_ISO: R173.1 R259.2 U40.14(~{DRDY}) U45.10(INC)
AIN2_MODE_3V3: R260.1 U45.4(INA) U48.19(B2)
AIN2_MODE_ISO: Q10.2(G) Q10.5(G) R174.2 R260.2 U45.13(OUTA) X63.1
AIN2_SCL_ISO: R169.1 R257.2 U40.16(SCL) U45.11(SCL2)
AIN2_SDA_ISO: R171.1 R258.2 U40.15(SDA) U45.14(SDA2)
I2C4_SCL: R183.1 U47.3(SCL1) X64.1 ; port I2C_4.I2C4_SCL
I2C4_SCL_3V3: R181.1 R251.1 R257.1 U43.6(SCL1) U45.6(SCL1) U47.6(SCL2)
I2C4_SDA: R184.1 U47.4(SDA1) X65.1 ; port I2C_4.I2C4_SDA
I2C4_SDA_3V3: R180.1 R252.1 R258.1 U43.3(SDA1) U45.3(SDA1) U47.5(SDA2)
PCIE_RESET#: R276.1 U48.4(A3) ; port PCIE_RESET#
PCIE_RESET_3V: U48.18(B3) ; port PCIE_RESET_3V
USB1_EN: R84.2 U48.5(A4) ; port USB1_EN
USB1_EN_3V: U48.17(B4) ; port USB1_EN_3V
NetC185_1: C185.1 R161.2 U39.7(AIN2)
NetC185_2: C185.2 R160.2 U39.6(AIN3)
NetC186_1: C186.1 JP1.2(C2) RA6.5 RA6.8 U39.10(AIN1)
NetC186_2: C186.2 RA6.4 RA6.6 U39.11(AIN0)
NetC187_1: C187.1 R163.2 U40.7(AIN2)
NetC187_2: C187.2 R162.2 U40.6(AIN3)
NetC188_1: C188.1 JP2.2(C2) RA7.5 RA7.8 U40.10(AIN1)
NetC188_2: C188.2 RA7.4 RA7.6 U40.11(AIN0)
NetC189_2: C189.2 R164.2 R166.2 U42.4(Adj)
NetC190_2: C190.2 R165.2 R167.2 U41.4(Adj)
NetM1_216: U48.2(A1) ; port AIN_CTRL.AIN1_MODE
NetM1_218: U48.3(A2) ; port AIN_CTRL.AIN2_MODE
NetM1_220: U48.6(A5) ; port AIN_CTRL.AIN1_DRDY
NetM1_222: U48.7(A6) ; port AIN_CTRL.AIN2_DRDY
NetQ9_3: Q9.3(D) Q9.6(D) R158.2 R160.1
NetQ10_3: Q10.3(D) Q10.6(D) R159.2 R162.1
NetR158_1: R158.1 R161.1 U37.5(OUT)
NetR159_1: R159.1 R163.1 U38.5(OUT)
NetR176_2: R176.2 U44.4(SYNC)
NetR177_1: R177.1 U44.5(SYNC_OK)
NetR178_2: R178.2 U46.4(SYNC)
NetR179_1: R179.1 U46.5(SYNC_OK)
NetR182_2: R182.2 U47.7(VREF2) U47.8(EN)
NetR273_2: R273.2 U48.21(~{OE})
NetR274_1: R274.1 U48.1(DIR1)
NetR275_1: R275.1 U48.10(DIR2)
NetRA6_1: RA6.1 RA6.3 RA6.7
NetRA7_1: RA7.1 RA7.3 RA7.7

Not connected (* = marked no-connect by the designer): U37 7(EN)* 8(~{SGOOD})*; U38 7(EN)* 8(~{SGOOD})*; U43 12(OUTB)*; U45 12(OUTB)*; U48 8(A7)* 9(A8)*

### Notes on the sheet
- (near RA6) Analog Input 1
- 3.3V
- (near U47) 1.8V
- ADC1
- (near U39) I2C Adr: 0x40
- (near X61) 3.18V
- (near RA7) Analog Input 2
- (near U40) ADC2
- (near U40) I2C Adr: 0x41
- 3.18V

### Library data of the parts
C183 C184 C189 C190 = 1602-Cap-0402-100pF: (-55 to 125 Degc AEC) CAP CER 100PF 50V 5% NPO 0402; Mfr: Murata; MfrNo: GCM1555C1H101JA16D; PN: 1602; Alt: UMK105CH101JVHF,GRT1555C1H101JA02D,GRT1555C1H101JA02J,CL05C101JB51PNC
C185-C188 C193-C199 C201 C203-C211 C213 C215 C216 = 1566-Cap-0402-100nF/50V: as C145 on sheet 620_Ethernet2
C191 C192 C200 C202 C212 C214 = 1314-Cap-0805-22uF/16V: (-55 to 85 DegC) CAP CER 22uF 16V X5R 0805; MfrNo: CL21A226MOQNNNE; Mfr: Samsung; PN: 1314; Alt: CL21A226MOCLRNC,CL21A226KOQNNNG,GRM21BR61C226ME44L,EMK212BBJ226MG-T
D24 D25 = 0581-SMAJ33CA: (-55 to 150 DegC) TVS DIODE 33VWM Vbrm:36.7V Vcl:53.3V 400W SMA; MfrNo: SMAJ33CA-E3/5A; Mfr: Vishay Semiconductor Diodes Division; PN: 581; Desc: (-55 to 150 DegC) TVS DIODE 33VWM Vbrm:36.7V Vstd:53.3VC SMA; Alt: SMAJ33CA-E3/61GICT-ND; Alt2: SMAJ33CABCT-ND; DR: SMAJ33CA-E3/5AGIDKR-ND; DR2: 625-SMAJ33CA-E3/5A
JP1 JP2 = 000-Jumper-Short: Jumper Wire
PTC5 PTC6 = 1423-PTC-0.1A-60V-1812: (-40 to 85 DegC) PTC Ih:0.1A, It:0.3A, 60V, 1812, 1.6-15ohm; MfrNo: 0ZCG0010FF2C; Mfr: Bel; PN: 1423; Alt: MPTS1812L010R,MPTS1812L010,1812L010/60DR,PTSA181260V010,MF-MSMF010-2,PFMF.010.2,MINISMDC010F-2,MINIASMDC010F-2
Q9 Q10 = 1146-NTZD3154NT1G: as Q14 on sheet 620_Ethernet2
R84 R174 R175 = 1539-Res-0402-86.6k: (-55 to 155 DegC AEC) RES 86.6K OHM 1% 1/16W 100ppm 0402; Mfr: Stackpole Electronics; MfrNo: RMCF0402FT86K6; Alt: AC0402FR-0786K6L,RK73H1ETTP8662F,ERJ-2RKF8662X; PN: 1539
R158 R159 = 1192-Res-1206-100ohm-0.01%-0.5W: RES SMD 100 OHM 0.01% 0.5W 1206 5ppm; Mfr: Stackpole Electronics; MfrNo: RNCF1206TKY100R; PN: 1192; Note: similar at lower prec: PN1432, TNPU1206100RBZEN00,TNPU1206100RAZEN00
R160-R163 R183 R184 = 1536-Res-0402-1.87K: as R220 on sheet 620_Ethernet2
R164 R165 = 1018-Res-0402-6.49K: (-55 to 155 DegC) RES SMD 6.49K OHM 1% 1/16W 0402; Mfr: Yageo; MfrNo: RC0402FR-076K49L; Alt: RMCF0402FT6K49,RC1005F6491CS,ERJ-2RKF6491X; PN: 1018
R166 R167 R273-R276 = 1572-Res-0402-10K: as R221 on sheet 620_Ethernet2
R168-R173 R180 R181 = 2233-Res-0402-4.7K: (-55 to 155 DegC) RES 4.70K OHM 1/16W 1% 0402 100ppm; MfrNo: RC0402FR-074K7L; Mfr: Yageo; PN: 2233
R176 R178 = 1650-Res-0402-1K: (-55 to 155 DegC AEC) RES 1K OHM 1% 1/16W 100ppm 0402; Mfr: TE Connectivity; MfrNo: CRGCQ0402F1K0; PN: 1650; Alt: CR0402AFX-1001GLF,AC0402FR-131KL,AC0402FR-071KL
R177 R179 = 1977-Res-0402-100K: as R127 on sheet 620_Ethernet2
R182 = 1367-Res-0603-200K: (-55 to 155 DegC) RES SMD 200K 1% 1/10W 0603 100ppm; Mfr: Stackpole Electronics; MfrNo: RMCF0603FT200K; Alt: CR0603-FX-2003ELF,RC0603FR-07200KL,RK73H1JTTD2003F; PN: 1367
R251-R262 = 0038-Res-1206-0.0ohm: (-55 to 155 DegC) RES 0.0 OHM 1/4W JUMPER 1206; Mfr: TE; MfrNo: 1623693-1; PN: 38; Alt: 311-0.0ERCT-ND; Alt2: RMCF1206ZT0R00CT-ND
RA6 RA7 = 2066A-ResArr-1206-10kohm-30kohm: (-55 to 125 DegC) RES ARRAY 4 RES 10 kOHM 30 kOHM 1206; Mfr: Vishay Beyschlag; MfrNo: ACASA1002S3002P100; PN: 2066
U37 U38 = 1870-TPS26614: (-40 to 155 DegC) IC Current Loop Protector 50V TSOT-23-8; Mfr: Texas Instruments; PN: 1870
U39 U40 = 1414-ADS1119: (-40 to 125 DegC) IC ADC 16BIT 4ch 1000SPS 16-TSSOP I2C Adr 0x40-0x4F IntRef SigmaDelta; Mfr: Texas Instruments; MfrNo: ADS1119IPWR; PN: 1414; Alt: ADS1119IPW, ADS1119IPWT
U41 U42 = 0619-AP2202K-ADJ: (-40 to 125 DegC) IC REG LDO ADJ 0.15A SOT23-5 13.2V; Mfr: Diodes Incorporated; MfrNo: AP2202K-ADJTRG1; PN: 619; DR: AP2202K-ADJTRG1DIDKR-ND; DR2: 621-AP2202K-ADJTRG1
U43 U45 = 2064-ISO1644DWR: (-40 to 125 DegC) DGTL ISO 5KV 5CH I2C 16SOIC; Mfr: Texas Instruments; PN: 2064
U44 U46 = 2065-UCC12040DVER: (-40 to 125 DegC) IC Isolated DC DC Converter-Output 3.3V, 5V 140mA, 4.5V-5.5V Input; Mfr: Texas Instruments; PN: 2065
U47 = 0972-PCA9306DCT: (-40 to 85 DegC) IC TRANSLTR BIDIRECTIONAL I2C SM8; MfrNo: PCA9306DCTR; Mfr: Texas Instruments; PN: 972
U48 = 2540-SN74AXC8T245RJWR: (-40 to 125 DegC) IC TRANSLATION TXRX 0.65-3.6V 24UQFN; Mfr: Texas Instruments; PN: 2540
X58-X65 = 000-TestPoint: Note: this is PCB footprint only, no parts to buy or assemble

## Sheet 320_RS-232.SchDoc: Ivy - Verdin Industrial Board Rev 1.1
size Letter; Organization: Toradex Solutions Inc.; Address1: 6415 Northwest Drive; Address2: Mississauga, ON, L4V 1X1; Address3: Canada
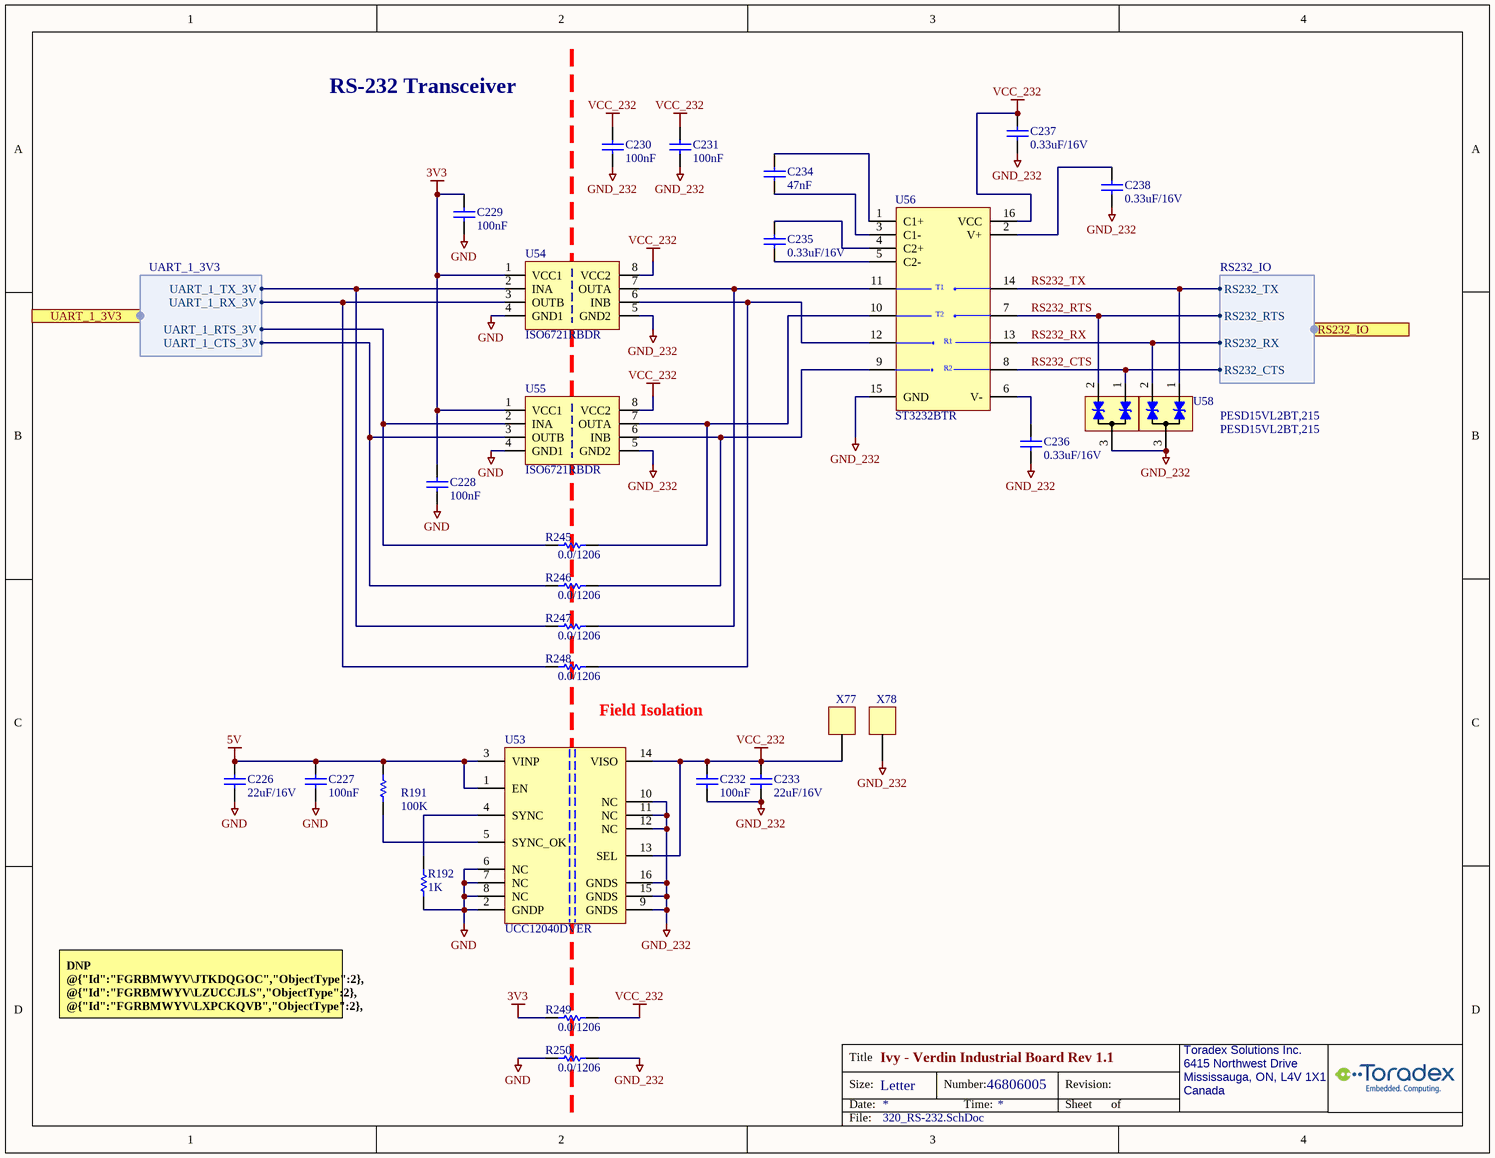
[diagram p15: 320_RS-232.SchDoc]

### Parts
C226  value 22uF/16V  [C/0805]  (hidden comment: 1314-Cap-0805-22uF/16V)
C227  100nF  [C0402_CAPC1005L]
C228  100nF  [C0402_CAPC1005L]
C229  100nF  [C0402_CAPC1005L]
C230  100nF  [C0402_CAPC1005L]
C231  100nF  [C0402_CAPC1005L]
C232  100nF  [C0402_CAPC1005L]
C233  value 22uF/16V  [C/0805]  (hidden comment: 1314-Cap-0805-22uF/16V)
C234  value 47nF  [C/0603]  (hidden comment: 0913-Cap-0603-47nF/50V-X7R)
C235  value 0.33uF/16V  [C/0603]  (hidden comment: 2823-Cap-0603-0.33uF/16V)
C236  value 0.33uF/16V  [C/0603]  (hidden comment: 2823-Cap-0603-0.33uF/16V)
C237  value 0.33uF/16V  [C/0603]  (hidden comment: 2823-Cap-0603-0.33uF/16V)
C238  value 0.33uF/16V  [C/0603]  (hidden comment: 2823-Cap-0603-0.33uF/16V)
R191  value 100K  [R0402_RESC1005L]  (hidden comment: 1977-Res-0402-100K)
R192  value 1K  [R0402_RESC1005L]  (hidden comment: 1650-Res-0402-1K)
R245  value 0.0/1206  [R/1206]  (hidden comment: 0038-Res-1206-0.0ohm)
R246  value 0.0/1206  [R/1206]  (hidden comment: 0038-Res-1206-0.0ohm)
R247  value 0.0/1206  [R/1206]  (hidden comment: 0038-Res-1206-0.0ohm)
R248  value 0.0/1206  [R/1206]  (hidden comment: 0038-Res-1206-0.0ohm)
R249  value 0.0/1206  [R/1206]  (hidden comment: 0038-Res-1206-0.0ohm)
R250  value 0.0/1206  [R/1206]  (hidden comment: 0038-Res-1206-0.0ohm)
U53  UCC12040DVER  [SOIC-16]
U54  ISO6721RBDR  [SOIC-8]
U55  ISO6721RBDR  [SOIC-8]
U56  ST3232BTR  [PW016]
U57  PESD15VL2BT,215  [SOT23_N]
U58  PESD15VL2BT,215  [SOT23_N]
X77  000-TestPoint  [TestPoint_1]  (value not drawn)
X78  000-TestPoint  [TestPoint_1]  (value not drawn)

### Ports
RS232_IO (harness RS232_IO), UART_1_3V3 (harness UART_1_3V3)

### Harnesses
UART_1_3V3: UART_1_RX_3V, UART_1_TX_3V, UART_1_RTS_3V, UART_1_CTS_3V
RS232_IO: RS232_RX, RS232_CTS, RS232_TX, RS232_RTS

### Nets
3V3: C228.1 C229.1 R249.2 U54.1(VCC1) U55.1(VCC1)
5V: C226.2 C227.1 R191.2 U53.1(EN) U53.3(VINP)
GND: C226.1 C227.2 C228.2 C229.2 R192.1 R250.2 U53.2(GNDP) U53.6(NC) U53.7(NC) U53.8(NC) U54.4(GND1) U55.4(GND1)
GND_232: C230.2 C231.2 C232.2 C233.1 C236.1 C237.1 C238.1 R250.1 U53.9(GNDS) U53.10(NC) U53.11(NC) U53.12(NC) U53.15(GNDS) U53.16(GNDS) U54.5(GND2) U55.5(GND2) U56.15(GND) U57.3(CC) U58.3(CC) X78.1
VCC_232: C230.1 C231.1 C232.1 C233.2 C237.2 R249.1 U53.13(SEL) U53.14(VISO) U54.8(VCC2) U55.8(VCC2) U56.16(VCC) X77.1
RS232_CTS: U56.8(R2IN) U57.1(K1) ; port RS232_IO.RS232_CTS
RS232_RTS: U56.7(T2OUT) U57.2(K2) ; port RS232_IO.RS232_RTS
RS232_RX: U56.13(R1IN) U58.2(K2) ; port RS232_IO.RS232_RX
RS232_TX: U56.14(T1OUT) U58.1(K1) ; port RS232_IO.RS232_TX
UART_1_CTS_3V: R246.2 U55.3(OUTB) ; port UART_1_3V3.UART_1_CTS_3V
UART_1_RTS_3V: R245.2 U55.2(INA) ; port UART_1_3V3.UART_1_RTS_3V
UART_1_RX_3V: R248.2 U54.3(OUTB) ; port UART_1_3V3.UART_1_RX_3V
UART_1_TX_3V: R247.2 U54.2(INA) ; port UART_1_3V3.UART_1_TX_3V
NetC234_1: C234.1 U56.3(C1-)
NetC234_2: C234.2 U56.1(C1+)
NetC235_1: C235.1 U56.5(C2-)
NetC235_2: C235.2 U56.4(C2+)
NetC236_2: C236.2 U56.6(V-)
NetC238_2: C238.2 U56.2(V+)
NetR191_1: R191.1 U53.5(SYNC_OK)
NetR192_2: R192.2 U53.4(SYNC)
NetR245_1: R245.1 U55.7(OUTA) U56.10(T2IN)
NetR246_1: R246.1 U55.6(INB) U56.9(R2OUT)
NetR247_1: R247.1 U54.7(OUTA) U56.11(T1IN)
NetR248_1: R248.1 U54.6(INB) U56.12(R1OUT)

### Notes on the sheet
- RS-232 Transceiver
- Field Isolation
- DNP @{"Id":"FGRBMWYV\JTKDQGOC","ObjectType":2}, @{"Id":"FGRBMWYV\LZUCCJLS","ObjectType":2}, @{"Id":"FGRBMWYV\LXPCKQVB","ObjectType":2}, @{"Id":"FGRBMWYV\FLONWOHB","ObjectType":2}, @{"Id":"FGRBMWYV\YEYATVRD","ObjectType":2}, @{"Id":"FGRBMWYV\DSLTWDMJ","ObjectType":2} are bypass jumpers when @{"Id":"FGRBMWYV\LXYJYHOV"}, @{"Id":"FGRBMWYV\GHWLQOMO"} and @{"Id":"FGRBMWYV\XDAZDTFI"} aren't mounted.

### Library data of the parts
C226 C233 = 1314-Cap-0805-22uF/16V: as C191 on sheet 840_ADC
C227-C232 = 1566-Cap-0402-100nF/50V: as C145 on sheet 620_Ethernet2
C234 = 0913-Cap-0603-47nF/50V-X7R: (-55 to 125 DegC) CAP CER 0.047UF 50V X7R 0603; Mfr: TDK Corporation; MfrNo: C1608X7R1H473K080AA; Alt: CL10B473KB8NNNL ,CL10B473KB8NNND,CL10B473KB8SFNC,CL10B473KB8NNNC; Alt2: CL10B473KB8WPNC,CC0603KRX7R9BB473,C1608X7R1H473K080AA,CL10B473KB8NNNC; PN: 913
C235-C238 = 2823-Cap-0603-0.33uF/16V: (-55 to 85 DegC) CAP CER 1UF 16V 10% X7R 0603; Mfr: Samsung; MfrNo: CL10B334KO8NNNC; PN: 2823
R191 = 1977-Res-0402-100K: as R127 on sheet 620_Ethernet2
R192 = 1650-Res-0402-1K: as R176 on sheet 840_ADC
R245-R250 = 0038-Res-1206-0.0ohm: as R251-R262 on sheet 840_ADC
U53 = 2065-UCC12040DVER: as U44 on sheet 840_ADC
U54 U55 = 2198-ISO6721RBDR: (-40 to 125 DegC) IC DGTL ISO GENERAL-PURPOSE, DUAL-CHANNEL, 1x In, 1x Out 1.71-5.5V; Mfr: Texas Instruments; PN: 2198
U56 = 0156-ST3232BTR: IC DRVR/RCVR RS232 LP 16-TSSOP; Mfr: ST; Alt: 296-13100-1-ND; Alt2: 296-23467-1-ND; PN: 156; TR: 497-6534-2-ND; DR: 497-6534-6-ND; DR2: 511-ST3232BT
U57 U58 = 2239-PESD15VL2BT,215: (-65 to 150 DegC) TVS DIODE 2-CH 15VWM 44VC ESD:30KV TO236AB; Mfr: Nexperia; PN: 2239
X77 X78 = 000-TestPoint: as X58-X65 on sheet 840_ADC

## Sheet 330_RS-485.SchDoc: Ivy - Verdin Industrial Board Rev 1.1
size Letter; Organization: Toradex Solutions Inc.; Address1: 6415 Northwest Drive; Address2: Mississauga, ON, L4V 1X1; Address3: Canada
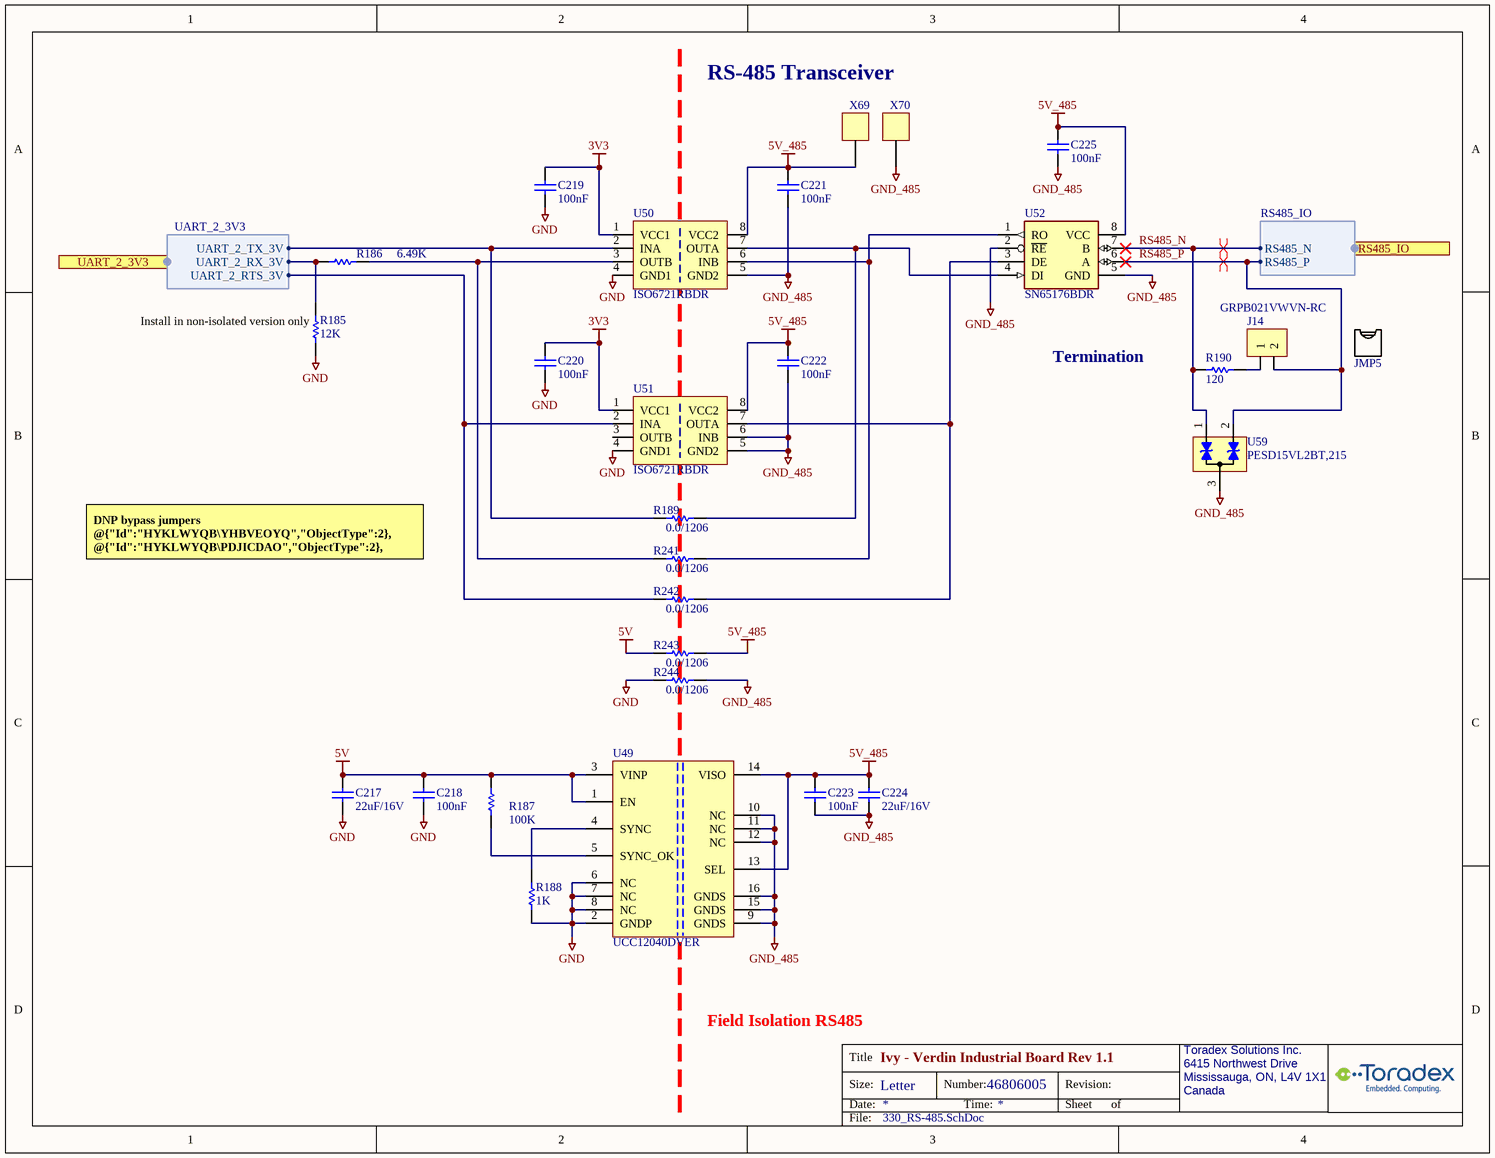
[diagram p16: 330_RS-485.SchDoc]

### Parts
C217  value 22uF/16V  [C/0805]  (hidden comment: 1314-Cap-0805-22uF/16V)
C218  100nF  [C0402_CAPC1005L]
C219  100nF  [C0402_CAPC1005L]
C220  100nF  [C0402_CAPC1005L]
C221  100nF  [C0402_CAPC1005L]
C222  100nF  [C0402_CAPC1005L]
C223  100nF  [C0402_CAPC1005L]
C224  value 22uF/16V  [C/0805]  (hidden comment: 1314-Cap-0805-22uF/16V)
C225  100nF  [C0402_CAPC1005L]
J14  GRPB021VWVN-RC  [CONN_WVN-RC_SUL]
JMP5  Shunt Jumper  (value not drawn)  (mechanical)
R185  value 12K  [R0402_RESC1005L]  (hidden comment: 1537-Res-0402-12K)
R186  value 6.49K  [R0402_RESC1005L]  (hidden comment: 1018-Res-0402-6.49K)
R187  value 100K  [R0402_RESC1005L]  (hidden comment: 1977-Res-0402-100K)
R188  value 1K  [R0402_RESC1005L]  (hidden comment: 1650-Res-0402-1K)
R189  value 0.0/1206  [R/1206]  (hidden comment: 0038-Res-1206-0.0ohm)
R190  value 120  [R0402_RESC1005L]  (hidden comment: 1552-Res-0402-120)
R241  value 0.0/1206  [R/1206]  (hidden comment: 0038-Res-1206-0.0ohm)
R242  value 0.0/1206  [R/1206]  (hidden comment: 0038-Res-1206-0.0ohm)
R243  value 0.0/1206  [R/1206]  (hidden comment: 0038-Res-1206-0.0ohm)
R244  value 0.0/1206  [R/1206]  (hidden comment: 0038-Res-1206-0.0ohm)
U49  UCC12040DVER  [SOIC-16]
U50  ISO6721RBDR  [SOIC-8]
U51  ISO6721RBDR  [SOIC-8]
U52  SN65176BDR  [SOIC-8]
U59  PESD15VL2BT,215  [SOT23_N]
X69  000-TestPoint  [TestPoint_1]  (value not drawn)
X70  000-TestPoint  [TestPoint_1]  (value not drawn)

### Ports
RS485_IO (harness RS485_IO), UART_2_3V3 (harness UART_2_3V3)

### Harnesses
UART_2_3V3: UART_2_RX_3V, UART_2_TX_3V, UART_2_RTS_3V
RS485_IO: RS485_N, RS485_P

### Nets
3V3: C219.1 C220.1 U50.1(VCC1) U51.1(VCC1)
5V: C217.2 C218.1 R187.2 R243.2 U49.1(EN) U49.3(VINP)
5V_485: C221.1 C222.1 C223.1 C224.2 C225.1 R243.1 U49.13(SEL) U49.14(VISO) U50.8(VCC2) U51.8(VCC2) U52.8(VCC) X69.1
GND: C217.1 C218.2 C219.2 C220.2 R185.1 R188.1 R244.2 U49.2(GNDP) U49.6(NC) U49.7(NC) U49.8(NC) U50.4(GND1) U51.4(GND1)
GND_485: C221.2 C222.2 C223.2 C224.1 C225.2 R244.1 U49.9(GNDS) U49.10(NC) U49.11(NC) U49.12(NC) U49.15(GNDS) U49.16(GNDS) U50.5(GND2) U51.5(GND2) U51.6(INB) U52.2(~{RE}) U52.5(GND) U59.3(CC) X70.1
RS485_N: R190.1 U52.7(B) U59.1(K1) ; port RS485_IO.RS485_N
RS485_P: J14.2 U52.6(A) U59.2(K2) ; port RS485_IO.RS485_P
UART_2_RTS_3V: R242.2 U51.2(INA) ; port UART_2_3V3.UART_2_RTS_3V
UART_2_RX_3V: R185.2 R186.2 ; port UART_2_3V3.UART_2_RX_3V
UART_2_TX_3V: R189.2 U50.2(INA) ; port UART_2_3V3.UART_2_TX_3V
NetJ14_1: J14.1 R190.2
NetR186_1: R186.1 R241.2 U50.3(OUTB)
NetR187_1: R187.1 U49.5(SYNC_OK)
NetR188_2: R188.2 U49.4(SYNC)
NetR189_1: R189.1 U50.7(OUTA) U52.4(DI)
NetR241_1: R241.1 U50.6(INB) U52.1(RO)
NetR242_1: R242.1 U51.7(OUTA) U52.3(DE)

Not connected (* = marked no-connect by the designer): U51 3(OUTB)

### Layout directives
differential pair; differential pair class RS485: RS485_N, RS485_P

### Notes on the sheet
- RS-485 Transceiver
- (near R185) Install in non-isolated version only
- Termination
- DNP bypass jumpers @{"Id":"HYKLWYQB\YHBVEOYQ","ObjectType":2}, @{"Id":"HYKLWYQB\PDJICDAO","ObjectType":2}, @{"Id":"HYKLWYQB\NNRCJBDI","ObjectType":2}, @{"Id":"HYKLWYQB\DUEUYHHI","ObjectType":2} and @{"Id":"HYKLWYQB\VTBHMBYQ","ObjectType":2} if @{"Id":"HYKLWYQB\RAJTRIYT"} , @{"Id":"HYKLWYQB\KFGBLUON"} and @{"Id":"HYKLWYQB\TYSTDRWN"} are't mounted.
  Ground isolation is not provided in that case.
- Field Isolation RS485

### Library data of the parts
C217 C224 = 1314-Cap-0805-22uF/16V: as C191 on sheet 840_ADC
C218-C223 C225 = 1566-Cap-0402-100nF/50V: as C145 on sheet 620_Ethernet2
J14 = 2350-CONN HEADER VERT 2POS 1.27MM: (-40 to 105 DegC) CONN HEADER VERT 2POS 1.27MM GOLD; Mfr: Sullins; PN: 2350
JMP5 = MECH-Shunt-Jumper-Black-2.54mm: Manufacturer Name: Assmann; Manufacturer Part No.: HMSC-G; PN: 20000617
R185 = 1537-Res-0402-12K: as R121 on sheet 620_Ethernet2
R186 = 1018-Res-0402-6.49K: as R164 on sheet 840_ADC
R187 = 1977-Res-0402-100K: as R127 on sheet 620_Ethernet2
R188 = 1650-Res-0402-1K: as R176 on sheet 840_ADC
R189 R241-R244 = 0038-Res-1206-0.0ohm: as R251-R262 on sheet 840_ADC
R190 = 1552-Res-0402-120: (-55 to 155 DegC AEC) RES 120 OHM 1% 1/16W 100ppm 0402; Mfr: Stackpole Electronics; MfrNo: RMCF0402FT120R; PN: 1552; Alt: AC0402FR-07120RL,CRGCQ0402F120R
U49 = 2065-UCC12040DVER: as U44 on sheet 840_ADC
U50 U51 = 2198-ISO6721RBDR: as U54 on sheet 320_RS-232
U52 = 2071-SN65176BDR: (-40 to 125 DegC) IC TXRX 5V RS485/422 8-SOIC; Mfr: Texas Instruments; PN: 2071
U59 = 2239-PESD15VL2BT,215: as U57 on sheet 320_RS-232
X69 X70 = 000-TestPoint: as X58-X65 on sheet 840_ADC

## Sheet 850_DIGIN.SchDoc: Ivy - Verdin Industrial Board Rev 1.1
size Letter; Organization: Toradex Solutions Inc.; Address1: 6415 Northwest Drive; Address2: Mississauga, ON, L4V 1X1; Address3: Canada
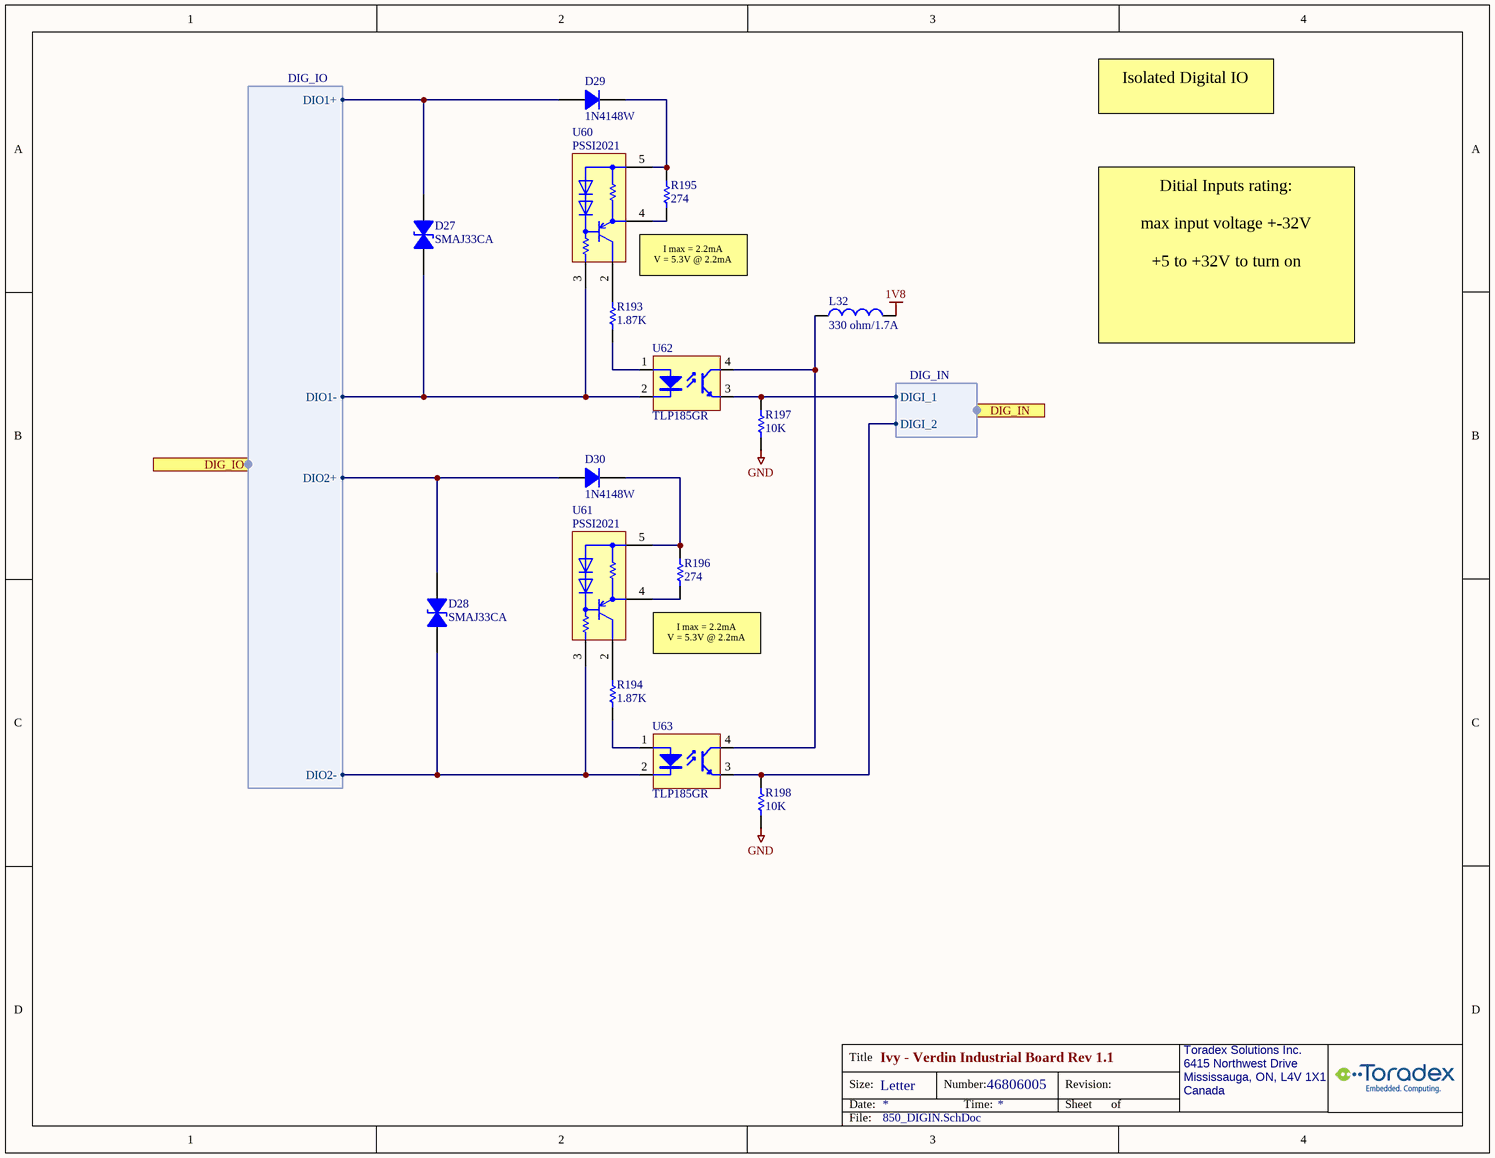
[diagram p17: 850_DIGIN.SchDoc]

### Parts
D27  SMAJ33CA  [SMAJ_TRANSIL]
D28  SMAJ33CA  [SMAJ_TRANSIL]
D29  1N4148W  [SOD123_ALT]
D30  1N4148W  [SOD123_ALT]
L32  value 330 ohm/1.7A  [INDC1608x095]  (hidden comment: 0405-Fer-0603-330ohm/1.7A)
R193  value 1.87K  [R0402_RESC1005L]  (hidden comment: 1536-Res-0402-1.87K)
R194  value 1.87K  [R0402_RESC1005L]  (hidden comment: 1536-Res-0402-1.87K)
R195  value 274  [R/0603]  (hidden comment: 0728-Res-0603-274ohm)
R196  value 274  [R/0603]  (hidden comment: 0728-Res-0603-274ohm)
R197  value 10K  [R0402_RESC1005L]  (hidden comment: 1572-Res-0402-10K)
R198  value 10K  [R0402_RESC1005L]  (hidden comment: 1572-Res-0402-10K)
U60  PSSI2021  [SOT353-5N]
U61  PSSI2021  [SOT353-5N]
U62  TLP185GR  [SOP254P700X210-4N]
U63  TLP185GR  [SOP254P700X210-4N]

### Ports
DIG_IN (harness DIG_IN), DIG_IO (harness DIG_IO)

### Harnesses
DIG_IN: DIGI_1, DIGI_2
DIG_IO: DIO1+, DIO1-, DIO2+, DIO2-

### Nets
1V8: L32.2
GND: R197.1 R198.1
DIGI_1: R197.2 U62.3(E) ; port DIG_IN.DIGI_1
DIGI_2: R198.2 U63.3(E) ; port DIG_IN.DIGI_2
DIO1+: D27.2 D29.1(A) ; port DIG_IO.DIO1+
DIO1-: D27.1 U60.3(Gnd) U62.2(K) ; port DIG_IO.DIO1-
DIO2+: D28.2 D30.1(A) ; port DIG_IO.DIO2+
DIO2-: D28.1 U61.3(Gnd) U63.2(K) ; port DIG_IO.DIO2-
NetD29_3: D29.3(K) R195.2 U60.5(Vs)
NetD30_3: D30.3(K) R196.2 U61.5(Vs)
NetL32_1: L32.1 U62.4(C) U63.4(C)
NetR193_1: R193.1 U62.1(A)
NetR193_2: R193.2 U60.2(Out)
NetR194_1: R194.1 U63.1(A)
NetR194_2: R194.2 U61.2(Out)
NetR195_1: R195.1 U60.4(Rext)
NetR196_1: R196.1 U61.4(Rext)

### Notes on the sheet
- Isolated Digital IO
- (near U60) I max = 2.2mA
  V = 5.3V @ 2.2mA
- Ditial Inputs rating:
  max input voltage +-32V
  +5 to +32V to turn on
- I max = 2.2mA
  V = 5.3V @ 2.2mA

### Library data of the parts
D27 D28 = 0581-SMAJ33CA: as D24 on sheet 840_ADC
D29 D30 = 1159-1N4148W: (-55 to 150 DegC) DIODE GEN PURP 100V 300MA SOD123; MfrNo: 1N4148W-7-F; Mfr: Diodes; PN: 1159; Alt: 1N4148WQ-7-F
L32 = 0405-Fer-0603-330ohm/1.7A: as L26 on sheet 620_Ethernet2
R193 R194 = 1536-Res-0402-1.87K: as R220 on sheet 620_Ethernet2
R195 R196 = 0728-Res-0603-274ohm: as R155 on sheet 820_MicroSD
R197 R198 = 1572-Res-0402-10K: (-55 to 155 DegC AEC) RES 10K OHM 1% 1/16W 100ppm 0402; MfrNo: RMCF0402FT10K0; Mfr: Stackpole Electronics; PN: 1572; Alt: AC0402FR-0710KL,AC0402FR-1310KL,CRGCQ0402F10K
U60 U61 = 0394-PSSI2021: (-65 to 150 DegC AEC)  IC CURRENT SOURCE SOT353 75V 50uA-50mA; MfrNo: PSSI2021SAY,115; Mfr: Nexperia USA Inc.; PN: 394
U62 U63 = 1170-Opto-TLP185GR: OPTOISO 3.75KV TRANS 6-SO 4 LEAD TR:100-300%@5mA, 80V, 3.7x7mm; MfrNo: TLP185(GR-TPL,SE; Mfr: Toshiba; PN: 1170

## Sheet 810_AUX_Connectors.SchDoc: Ivy - Verdin Industrial Board Rev 1.1
size Letter; Organization: Toradex Solutions Inc.; Address1: 6415 Northwest Drive; Address2: Mississauga, ON, L4V 1X1; Address3: Canada
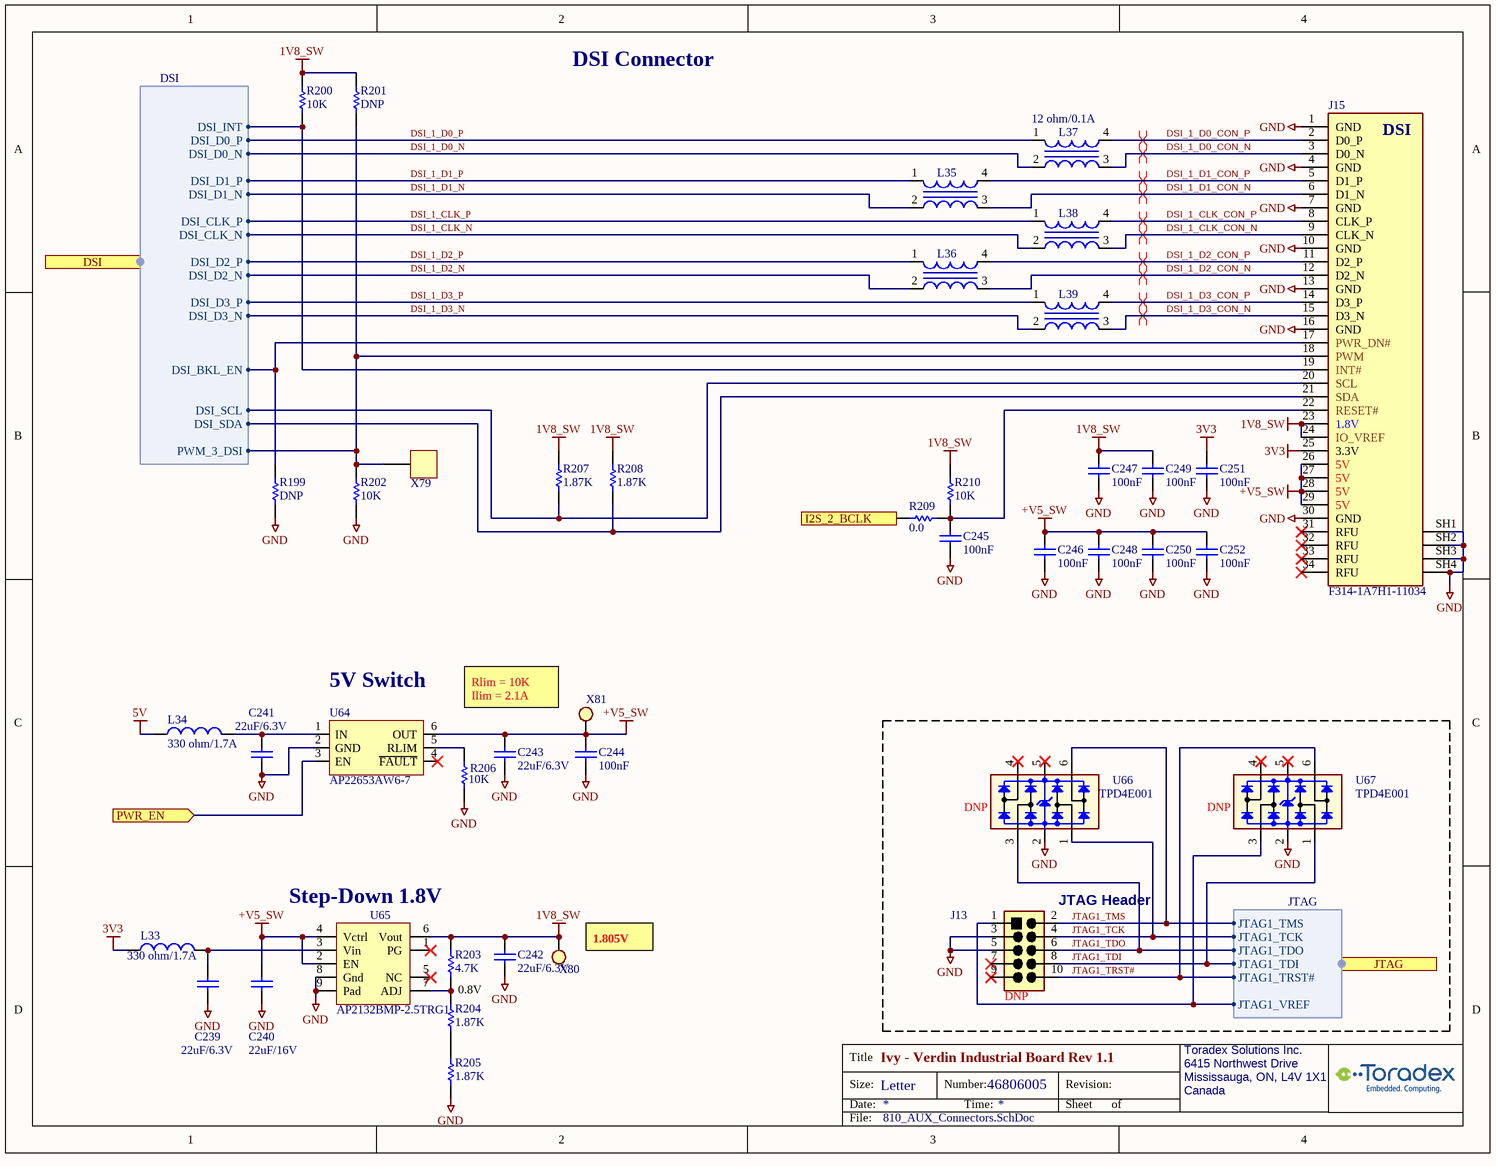
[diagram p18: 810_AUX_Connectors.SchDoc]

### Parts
C239  22uF/6.3V  [C0402_CAPC1005L]
C240  value 22uF/16V  [C/0805]  (hidden comment: 1314-Cap-0805-22uF/16V)
C241  22uF/6.3V  [C0402_CAPC1005L]
C242  22uF/6.3V  [C0402_CAPC1005L]
C243  22uF/6.3V  [C0402_CAPC1005L]
C244  100nF  [C0402_CAPC1005L]
C245  100nF  [C0402_CAPC1005L]
C246  100nF  [C0402_CAPC1005L]
C247  100nF  [C0402_CAPC1005L]
C248  100nF  [C0402_CAPC1005L]
C249  100nF  [C0402_CAPC1005L]
C250  100nF  [C0402_CAPC1005L]
C251  100nF  [C0402_CAPC1005L]
C252  100nF  [C0402_CAPC1005L]
J13  FTSH-105-01-L-DV-K  [SAMTEC_FTSH-105-01-L-DV-K-TR]  (value not drawn)  (no BOM)
J15  F314-1A7H1-11034  [AMPHENOL_F314-1A7H1-11034]
L33  value 330 ohm/1.7A  [INDC1608x095]  (hidden comment: 0405-Fer-0603-330ohm/1.7A)
L34  value 330 ohm/1.7A  [INDC1608x095]  (hidden comment: 0405-Fer-0603-330ohm/1.7A)
L35  12 ohm/0.1A  [COIL0302]  (value not drawn)
L36  12 ohm/0.1A  [COIL0302]  (value not drawn)
L37  12 ohm/0.1A  [COIL0302]
L38  12 ohm/0.1A  [COIL0302]  (value not drawn)
L39  12 ohm/0.1A  [COIL0302]  (value not drawn)
R199  value DNP  [R0402_RESC1005L]  (hidden comment: 0000-Res-0402-DNP)
R200  value 10K  [R0402_RESC1005L]  (hidden comment: 1572-Res-0402-10K)
R201  value DNP  [R0402_RESC1005L]  (hidden comment: 0000-Res-0402-DNP)
R202  value 10K  [R0402_RESC1005L]  (hidden comment: 1572-Res-0402-10K)
R203  value 4.7K  [R0402_RESC1005L]  (hidden comment: 2233-Res-0402-4.7K)
R204  value 1.87K  [R0402_RESC1005L]  (hidden comment: 1536-Res-0402-1.87K)
R205  value 1.87K  [R0402_RESC1005L]  (hidden comment: 1536-Res-0402-1.87K)
R206  value 10K  [R0402_RESC1005L]  (hidden comment: 1572-Res-0402-10K)
R207  value 1.87K  [R0402_RESC1005L]  (hidden comment: 1536-Res-0402-1.87K)
R208  value 1.87K  [R0402_RESC1005L]  (hidden comment: 1536-Res-0402-1.87K)
R209  value 0.0  [R/0603]  (hidden comment: 0195-Res-0603-0.0ohm)
R210  value 10K  [R0402_RESC1005L]  (hidden comment: 1572-Res-0402-10K)
U64  AP22653AW6-7  [sot23-6]
U65  AP2132BMP-2.5TRG1  [SOP-9 TP_ALT]
U66  TPD4E001  [SOT23-6]  (no BOM)
U67  TPD4E001  [SOT23-6]  (no BOM)
X79  000-TestPoint  [TestPoint_1]  (value not drawn)
X80  000-TestPoint2  [TestPoint_3]  (value not drawn)
X81  000-TestPoint2  [TestPoint_3]  (value not drawn)

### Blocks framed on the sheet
JTAG Header: J13 U66 U67

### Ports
DSI (harness DSI), I2S_2_BCLK (in), JTAG (harness JTAG), PWR_EN (in)

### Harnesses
JTAG: JTAG1_TDI, JTAG1_TRST#, JTAG1_TDO, JTAG1_VREF, JTAG1_TCK, JTAG1_TMS
DSI: DSI_SDA, DSI_SCL, DSI_BKL_EN, PWM_3_DSI, DSI_INT, DSI_D3_N, DSI_D3_P, DSI_D2_N, DSI_D2_P, DSI_CLK_N, DSI_CLK_P, DSI_D1_N, DSI_D1_P, DSI_D0_N, DSI_D0_P

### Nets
1V8_SW: C242.2 C247.2 C249.2 J15.23(1.8V) J15.24(IO_VREF) R200.2 R201.2 R203.2 R207.2 R208.2 R210.2 U65.6(Vout) X80.1
3V3: C251.2 J15.25(3.3V) L33.1
5V: L34.1
+V5_SW: C240.2 C243.2 C244.2 C246.2 C248.2 C250.2 C252.2 J15.26(5V) J15.27(5V) J15.28(5V) J15.29(5V) U64.6(OUT) U65.2(EN) U65.4(Vctrl) X81.1
GND: C239.1 C240.1 C241.1 C242.1 C243.1 C244.1 C245.1 C246.1 C247.1 C248.1 C249.1 C250.1 C251.1 C252.1 J13.3 J13.5 J15.1(GND) J15.4(GND) J15.7(GND) J15.10(GND) J15.13(GND) J15.16(GND) J15.30(GND) J15.SH1 J15.SH2 J15.SH3 J15.SH4 R199.1 R202.1 R205.1 R206.1 U64.2(GND) U65.8(Gnd) U65.9(Pad) U66.2 U67.2
DSI_1_CLK_CON_N: J15.9(CLK_N) L38.3
DSI_1_CLK_CON_P: J15.8(CLK_P) L38.4
DSI_1_CLK_N: L38.2 ; port DSI.DSI_CLK_N
DSI_1_CLK_P: L38.1 ; port DSI.DSI_CLK_P
DSI_1_D0_CON_N: J15.3(D0_N) L37.3
DSI_1_D0_CON_P: J15.2(D0_P) L37.4
DSI_1_D0_N: L37.2 ; port DSI.DSI_D0_N
DSI_1_D0_P: L37.1 ; port DSI.DSI_D0_P
DSI_1_D1_CON_N: J15.6(D1_N) L35.3
DSI_1_D1_CON_P: J15.5(D1_P) L35.4
DSI_1_D1_N: L35.2 ; port DSI.DSI_D1_N
DSI_1_D1_P: L35.1 ; port DSI.DSI_D1_P
DSI_1_D2_CON_N: J15.12(D2_N) L36.3
DSI_1_D2_CON_P: J15.11(D2_P) L36.4
DSI_1_D2_N: L36.2 ; port DSI.DSI_D2_N
DSI_1_D2_P: L36.1 ; port DSI.DSI_D2_P
DSI_1_D3_CON_N: J15.15(D3_N) L39.3
DSI_1_D3_CON_P: J15.14(D3_P) L39.4
DSI_1_D3_N: L39.2 ; port DSI.DSI_D3_N
DSI_1_D3_P: L39.1 ; port DSI.DSI_D3_P
DSI_BKL_EN: J15.17(PWR_DN#) R199.2 ; port DSI.DSI_BKL_EN
DSI_INT: J15.19(INT#) R200.1 ; port DSI.DSI_INT
DSI_SCL: J15.20(SCL) R207.1 ; port DSI.DSI_SCL
DSI_SDA: J15.21(SDA) R208.1 ; port DSI.DSI_SDA
I2S_2_BCLK: R209.1 ; port I2S_2_BCLK
JTAG1_TCK: J13.4 U66.1 ; port JTAG.JTAG1_TCK
JTAG1_TDI: J13.8 U67.1 ; port JTAG.JTAG1_TDI
JTAG1_TDO: J13.6 U66.3 ; port JTAG.JTAG1_TDO
JTAG1_TMS: J13.2 U66.6 ; port JTAG.JTAG1_TMS
JTAG1_TRST#: J13.10 U67.6 ; port JTAG.JTAG1_TRST#
PWM_3_DSI: J15.18(PWM) R201.1 R202.2 X79.1 ; port DSI.PWM_3_DSI
PWR_EN: U64.3(EN) ; port PWR_EN
NetC239_2: C239.2 L33.2 U65.3(Vin)
NetC241_2: C241.2 L34.2 U64.1(IN)
NetC245_2: C245.2 J15.22(RESET#) R209.2 R210.1
NetJ13_1: J13.1 U67.3 ; port JTAG.JTAG1_VREF
NetR203_1: R203.1 R204.2 U65.7(ADJ)
NetR204_1: R204.1 R205.2
NetR206_2: R206.2 U64.5(RLIM)

Not connected (* = marked no-connect by the designer): J13 7* 9*; J15 31(RFU)* 32(RFU)* 33(RFU)* 34(RFU)*; U64 4(~{FAULT})*; U65 1(PG)* 5(NC)*; U66 4* 5*; U67 4* 5*

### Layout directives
differential pair; differential pair class DSI; differential pair class DSI_1_CON: DSI_1_CLK_CON_N, DSI_1_CLK_CON_P, DSI_1_D0_CON_N, DSI_1_D0_CON_P, DSI_1_D1_CON_N, DSI_1_D1_CON_P, DSI_1_D2_CON_N, DSI_1_D2_CON_P, DSI_1_D3_CON_N, DSI_1_D3_CON_P

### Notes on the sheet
- DSI Connector
- (near U64) 5V Switch
- Rlim = 10K
  Ilim = 2.1A
- (near U66) DNP
- (near U67) DNP
- Step-Down 1.8V
- (near X80) 1.805V
- 0.8V
- (near J13) DNP

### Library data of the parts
C239 C241-C243 = 2404-Cap-0402-22uF/6.3V: as C181 on sheet 820_MicroSD
C240 = 1314-Cap-0805-22uF/16V: as C191 on sheet 840_ADC
C244-C252 = 1566-Cap-0402-100nF/50V: as C145 on sheet 620_Ethernet2
J13 = 1486-Conn-Header 5X2 SMT Vert: (-55 to 125 DegC) CONN HEADER VERT 10POS 2x5 1.27MM SMT Gold Shroud; MfrNo: FTSH-105-01-L-DV-K-TR; Mfr: Samtec; PN: 1486
J15 = 2373-F314-1A7H1-11034: (-40 to 105 DegC) CONN FFC SIDE 34POS 0.5MM VERT; Mfr: Amphenol ICC / FCI; PN: 2373
L33 L34 = 0405-Fer-0603-330ohm/1.7A: as L26 on sheet 620_Ethernet2
L35-L39 = 1371-Ind-0.8x0.6-12ohm/0.1A-Choke: (-40 to 85 DegC) Ind CMC Choke 12 Ohm 0.1A 1ohm 0.85x0.65x0.5mm; MfrNo: EXC-14CH120U; Mfr: Panasonic; PN: 1371
R199 R201 = 0000-Res-0402-DNP: RES 0402
R200 R202 R206 R210 = 1572-Res-0402-10K: as R221 on sheet 620_Ethernet2
R203 = 2233-Res-0402-4.7K: as R168-R173 on sheet 840_ADC
R204 R205 R207 R208 = 1536-Res-0402-1.87K: as R220 on sheet 620_Ethernet2
R209 = 0195-Res-0603-0.0ohm: RES 0.0 OHM 1/10W JUMP 0603; Mfr: Samsung; MfrNo: RC1608J000CS; Alt: 311-0.0GRCT-ND; Alt2: A106051CT-ND; PN: 195; TR: 1276-3510-2-ND
U64 = 1475-AP22653: as U35 on sheet 820_MicroSD
U65 = 1467-AP2132BMP-2.5: as U29 on sheet 620_Ethernet2
U66 U67 = 0740-TPD4E001: (-40 to 125 DegC AEC) TVS DIODE 5.5VWM 16VC SOT-23-6; MfrNo: TPD4E001QDBVRQ1; Mfr: Texas Instruments; PN: 740; Alt: TPD4E001DBVR
X79 = 000-TestPoint: as X58-X65 on sheet 840_ADC
X80 X81 = 000-TestPoint2: as X51-X53 on sheet 620_Ethernet2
